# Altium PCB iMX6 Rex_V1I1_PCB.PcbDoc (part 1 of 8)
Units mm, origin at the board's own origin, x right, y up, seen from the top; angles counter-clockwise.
Board outline 70 x 40 mm, 12 copper layers (L1, L2, L3, L4, L5 (PWR), L6 (PWR), L7 (PWR), L8 (PWR), L9, L10, L11, L12), stack 1.566 mm thick; 473 components, 409 nets, 2294 pads, 1880 vias.
Unrouted connection lines stored in the file: 7.
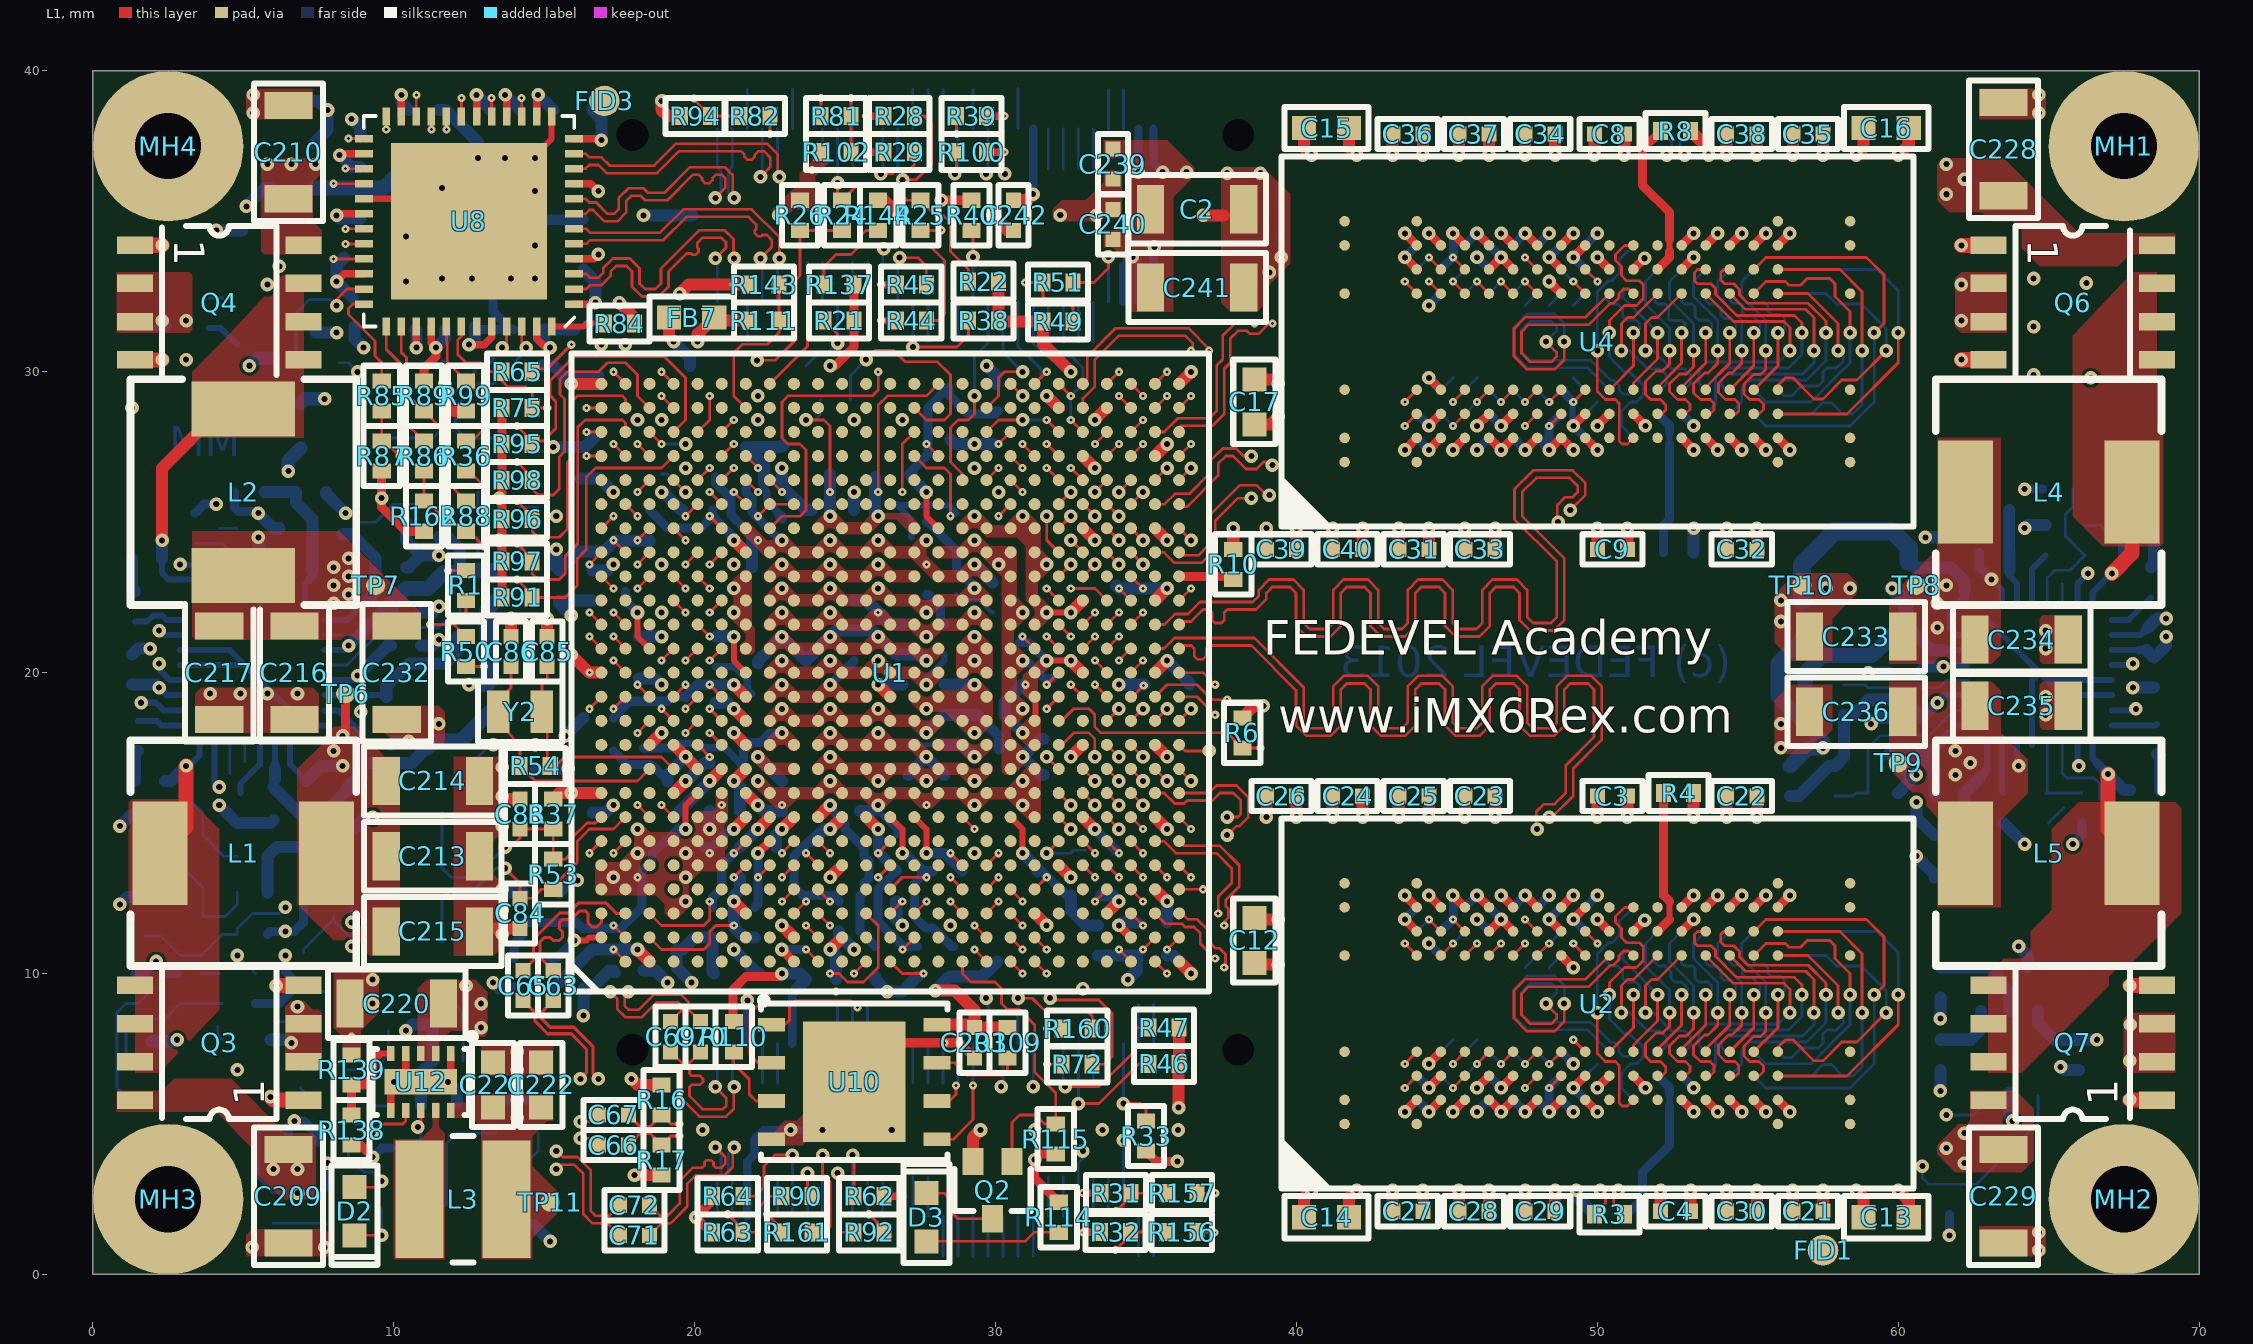
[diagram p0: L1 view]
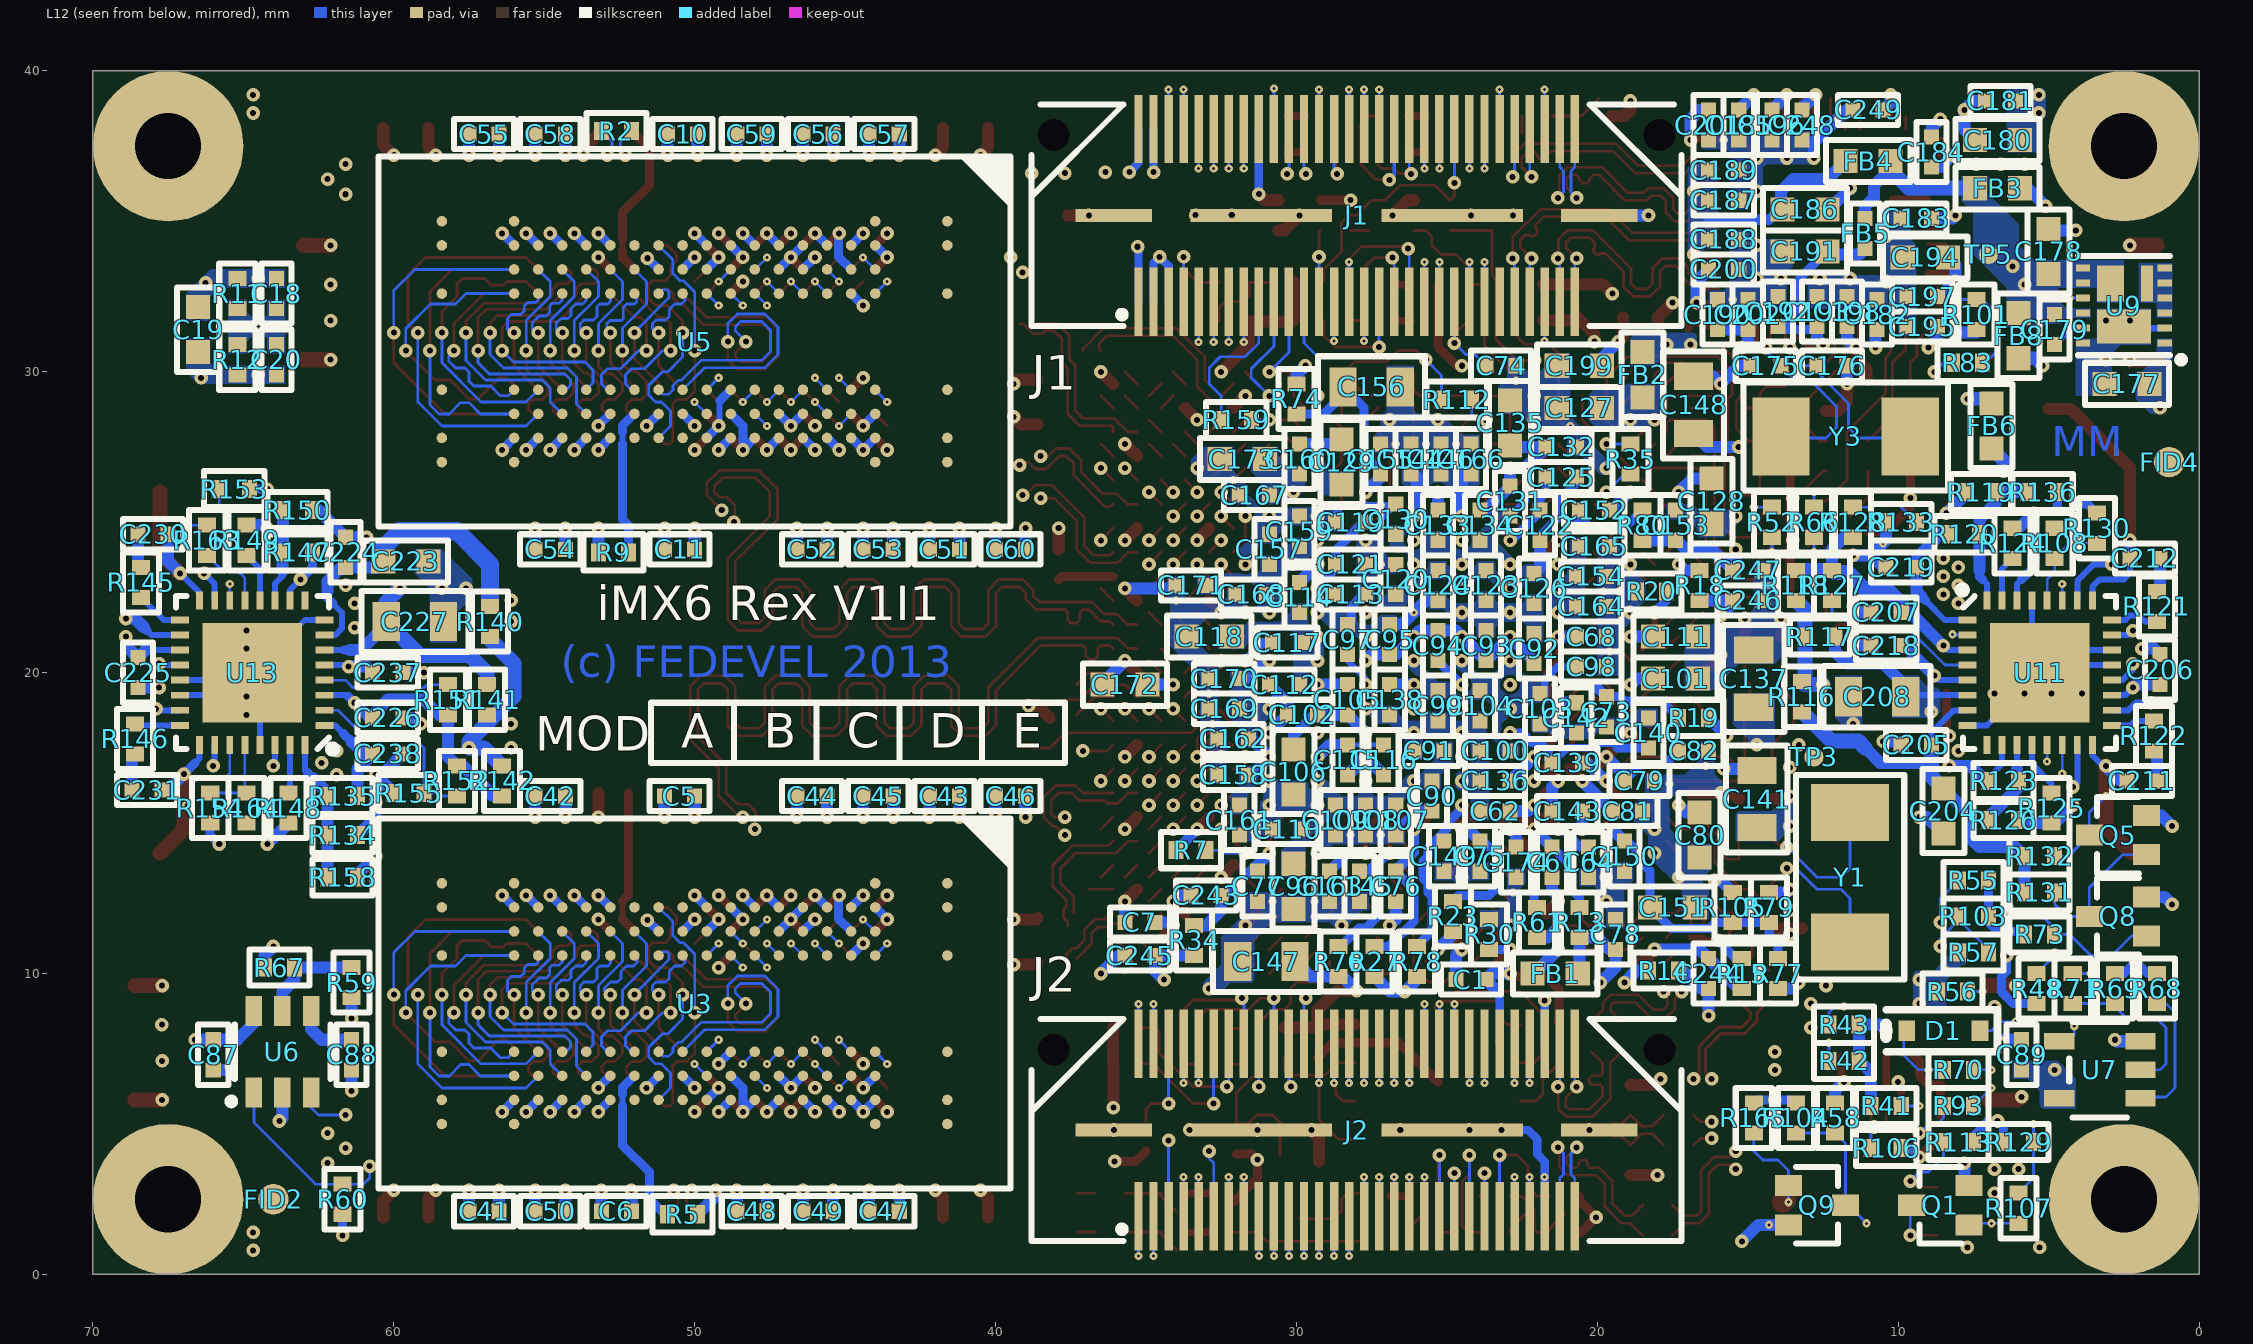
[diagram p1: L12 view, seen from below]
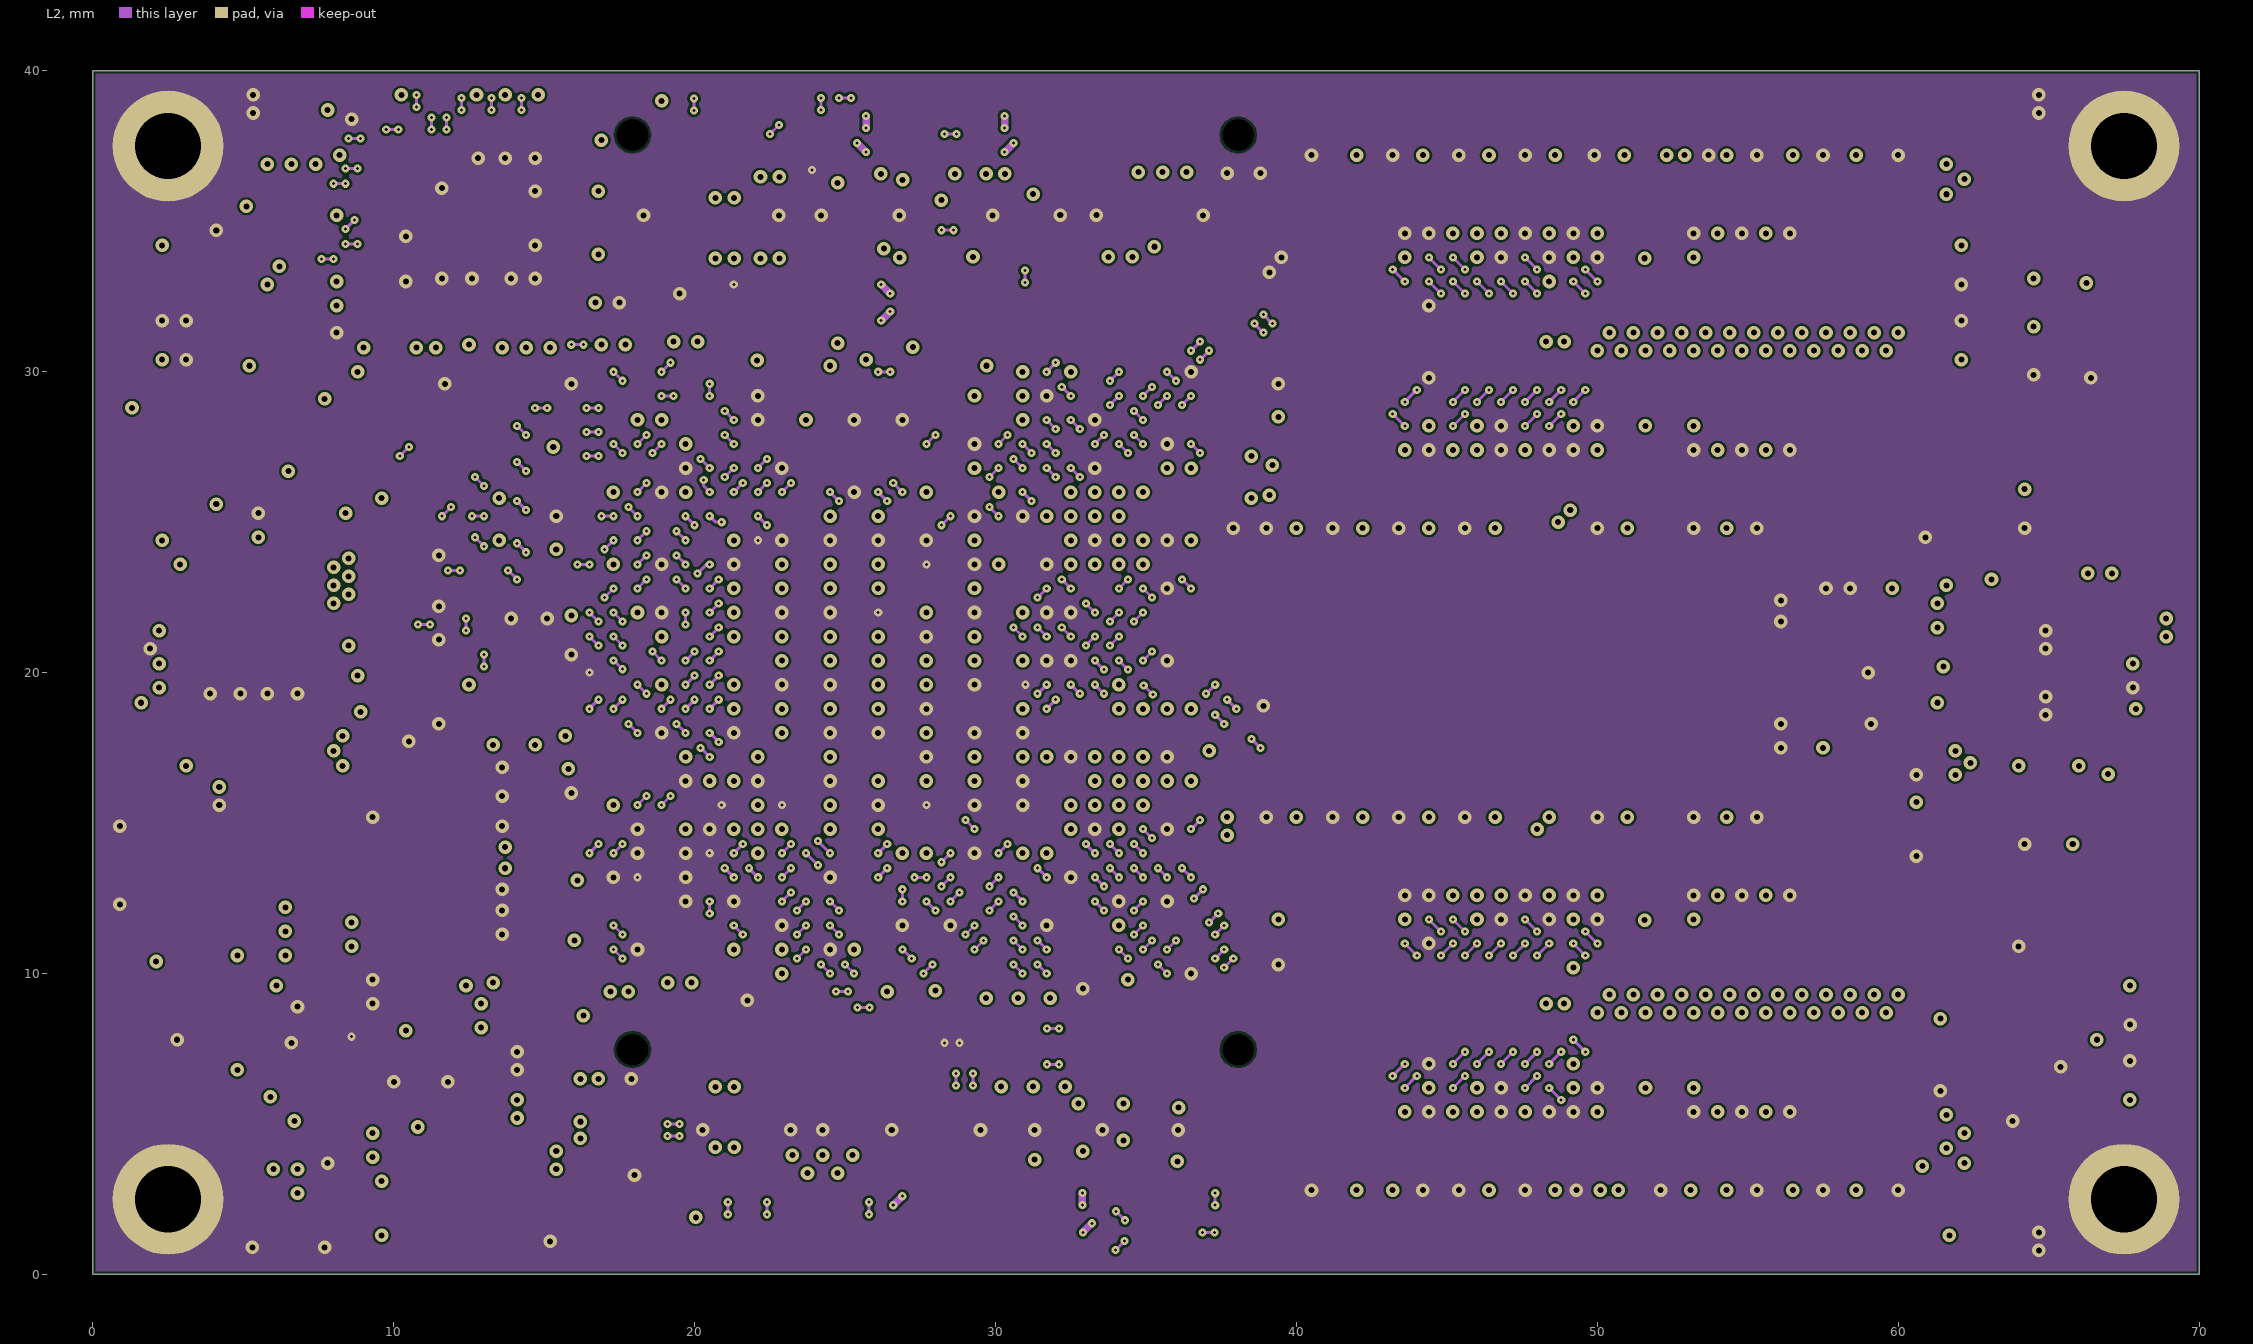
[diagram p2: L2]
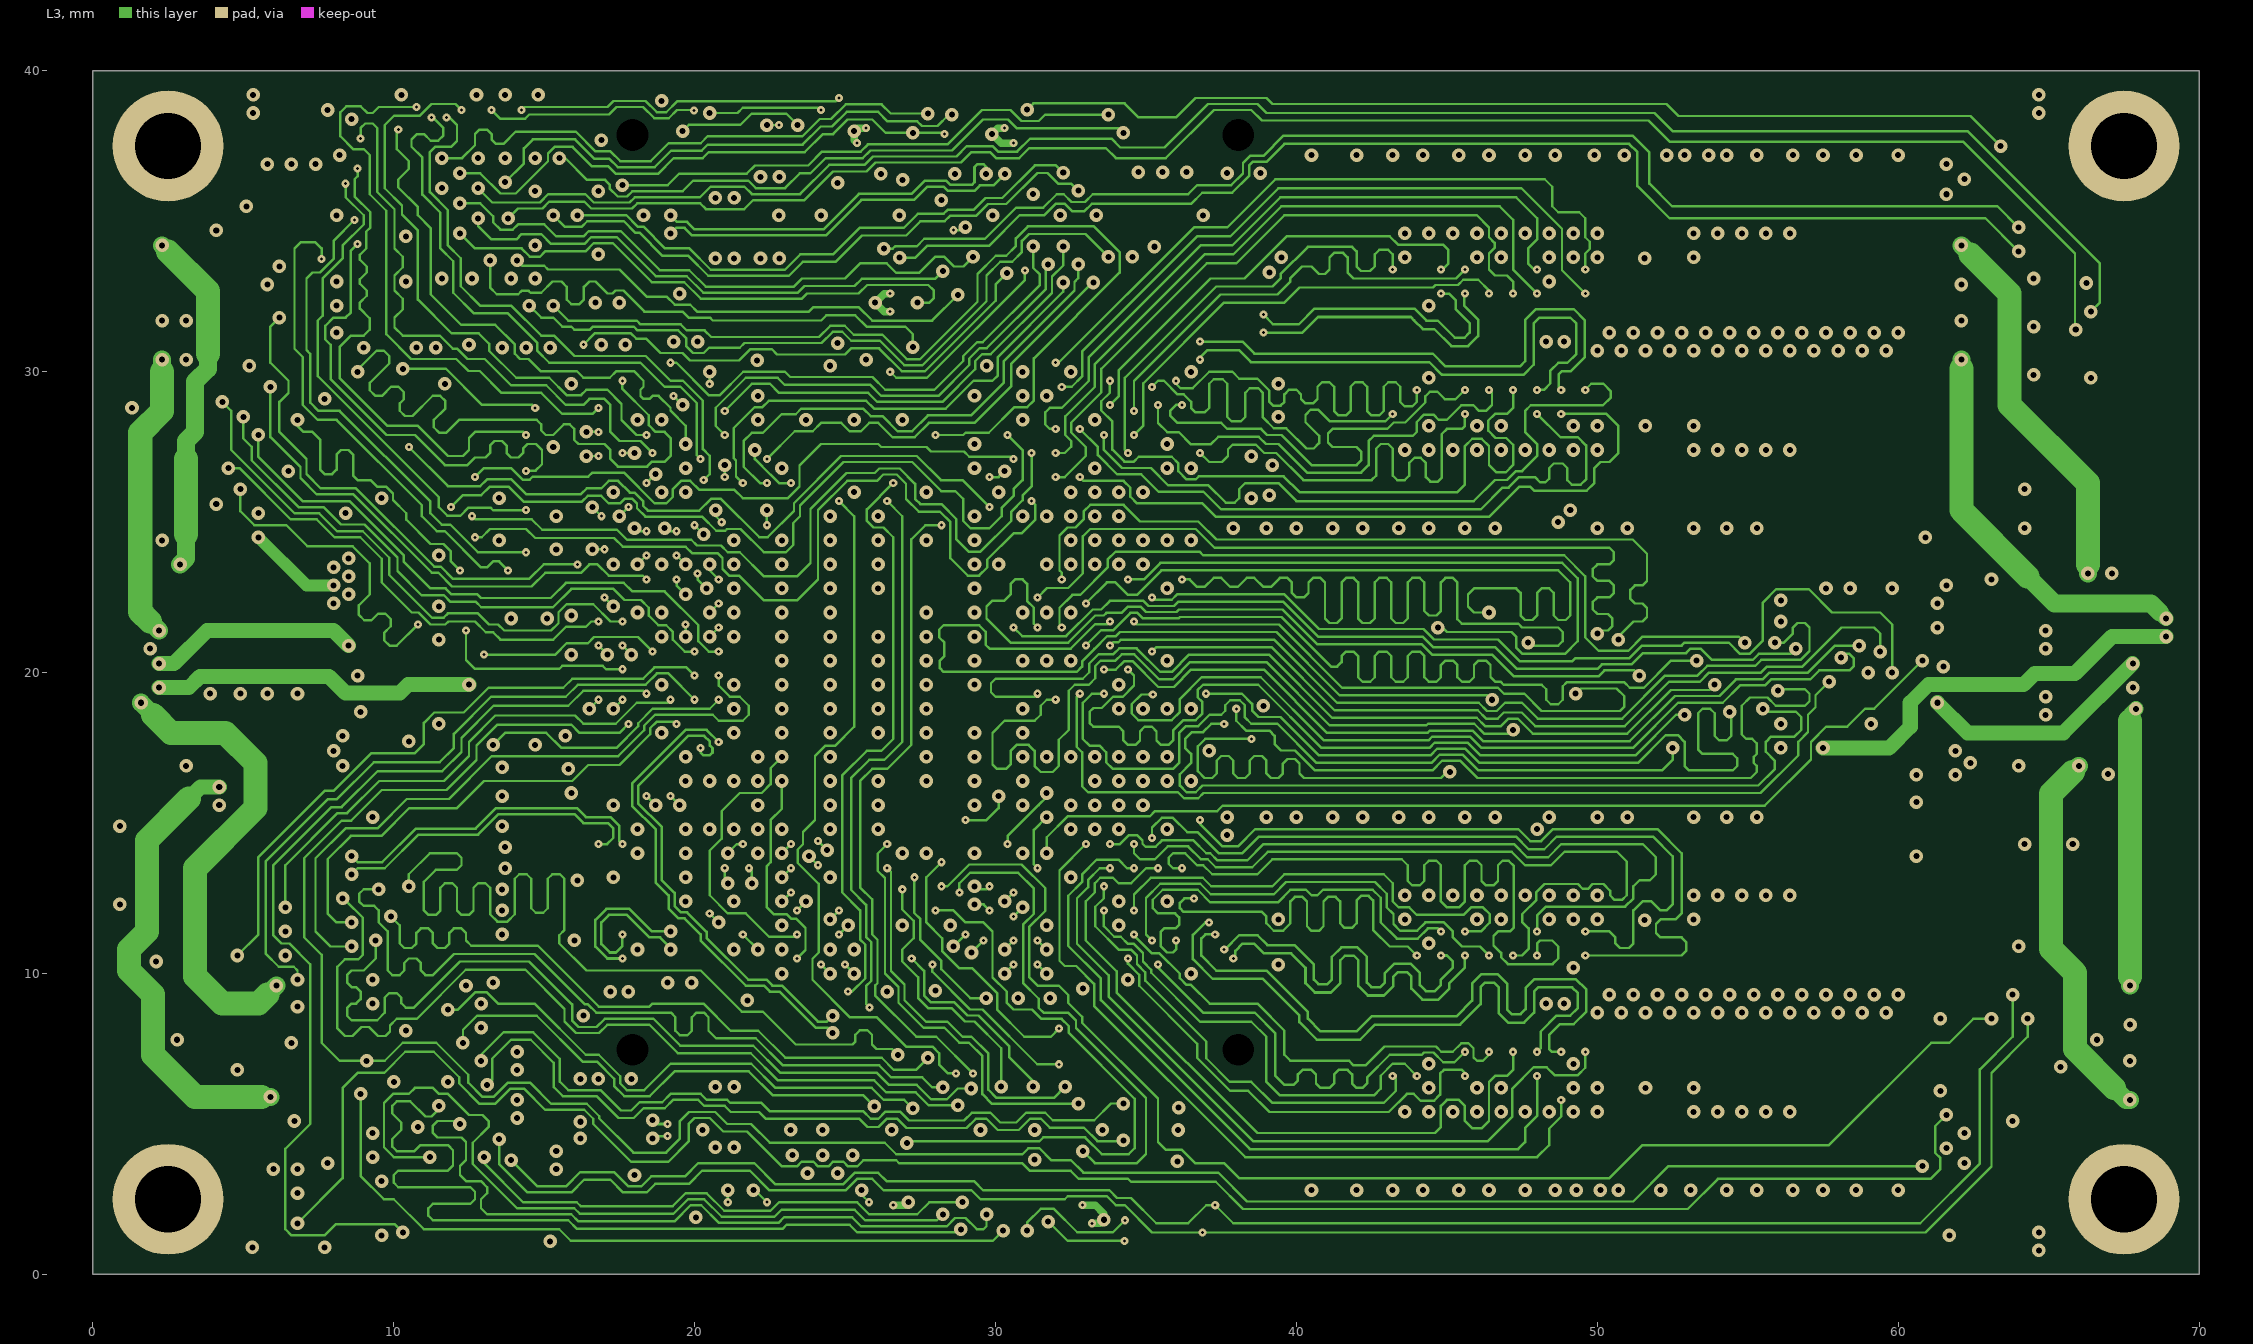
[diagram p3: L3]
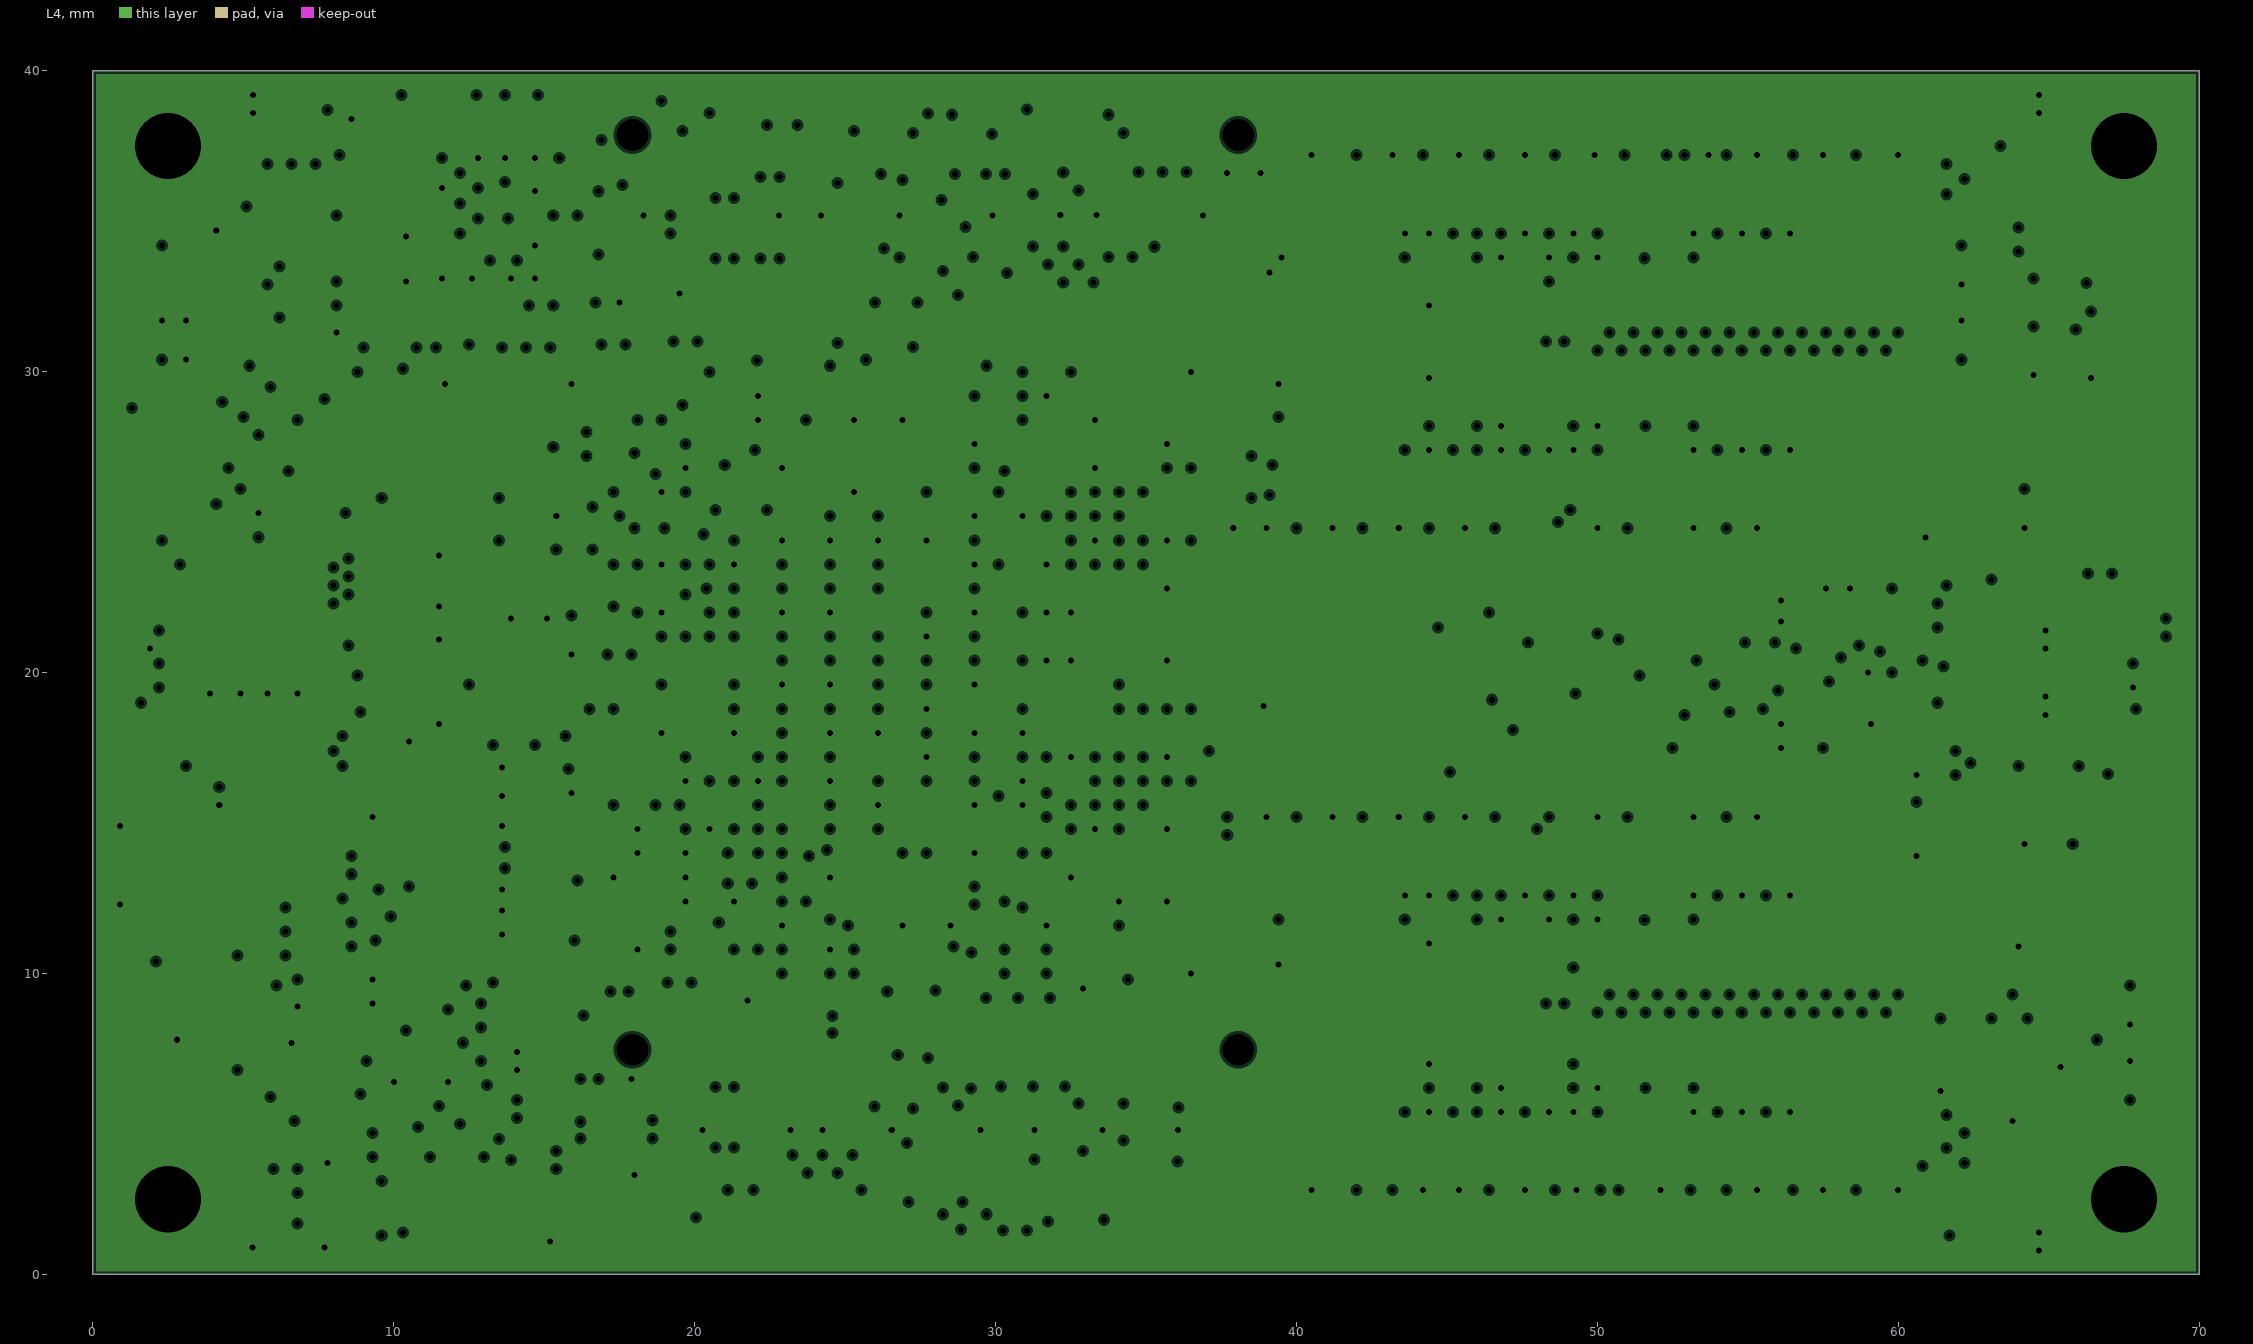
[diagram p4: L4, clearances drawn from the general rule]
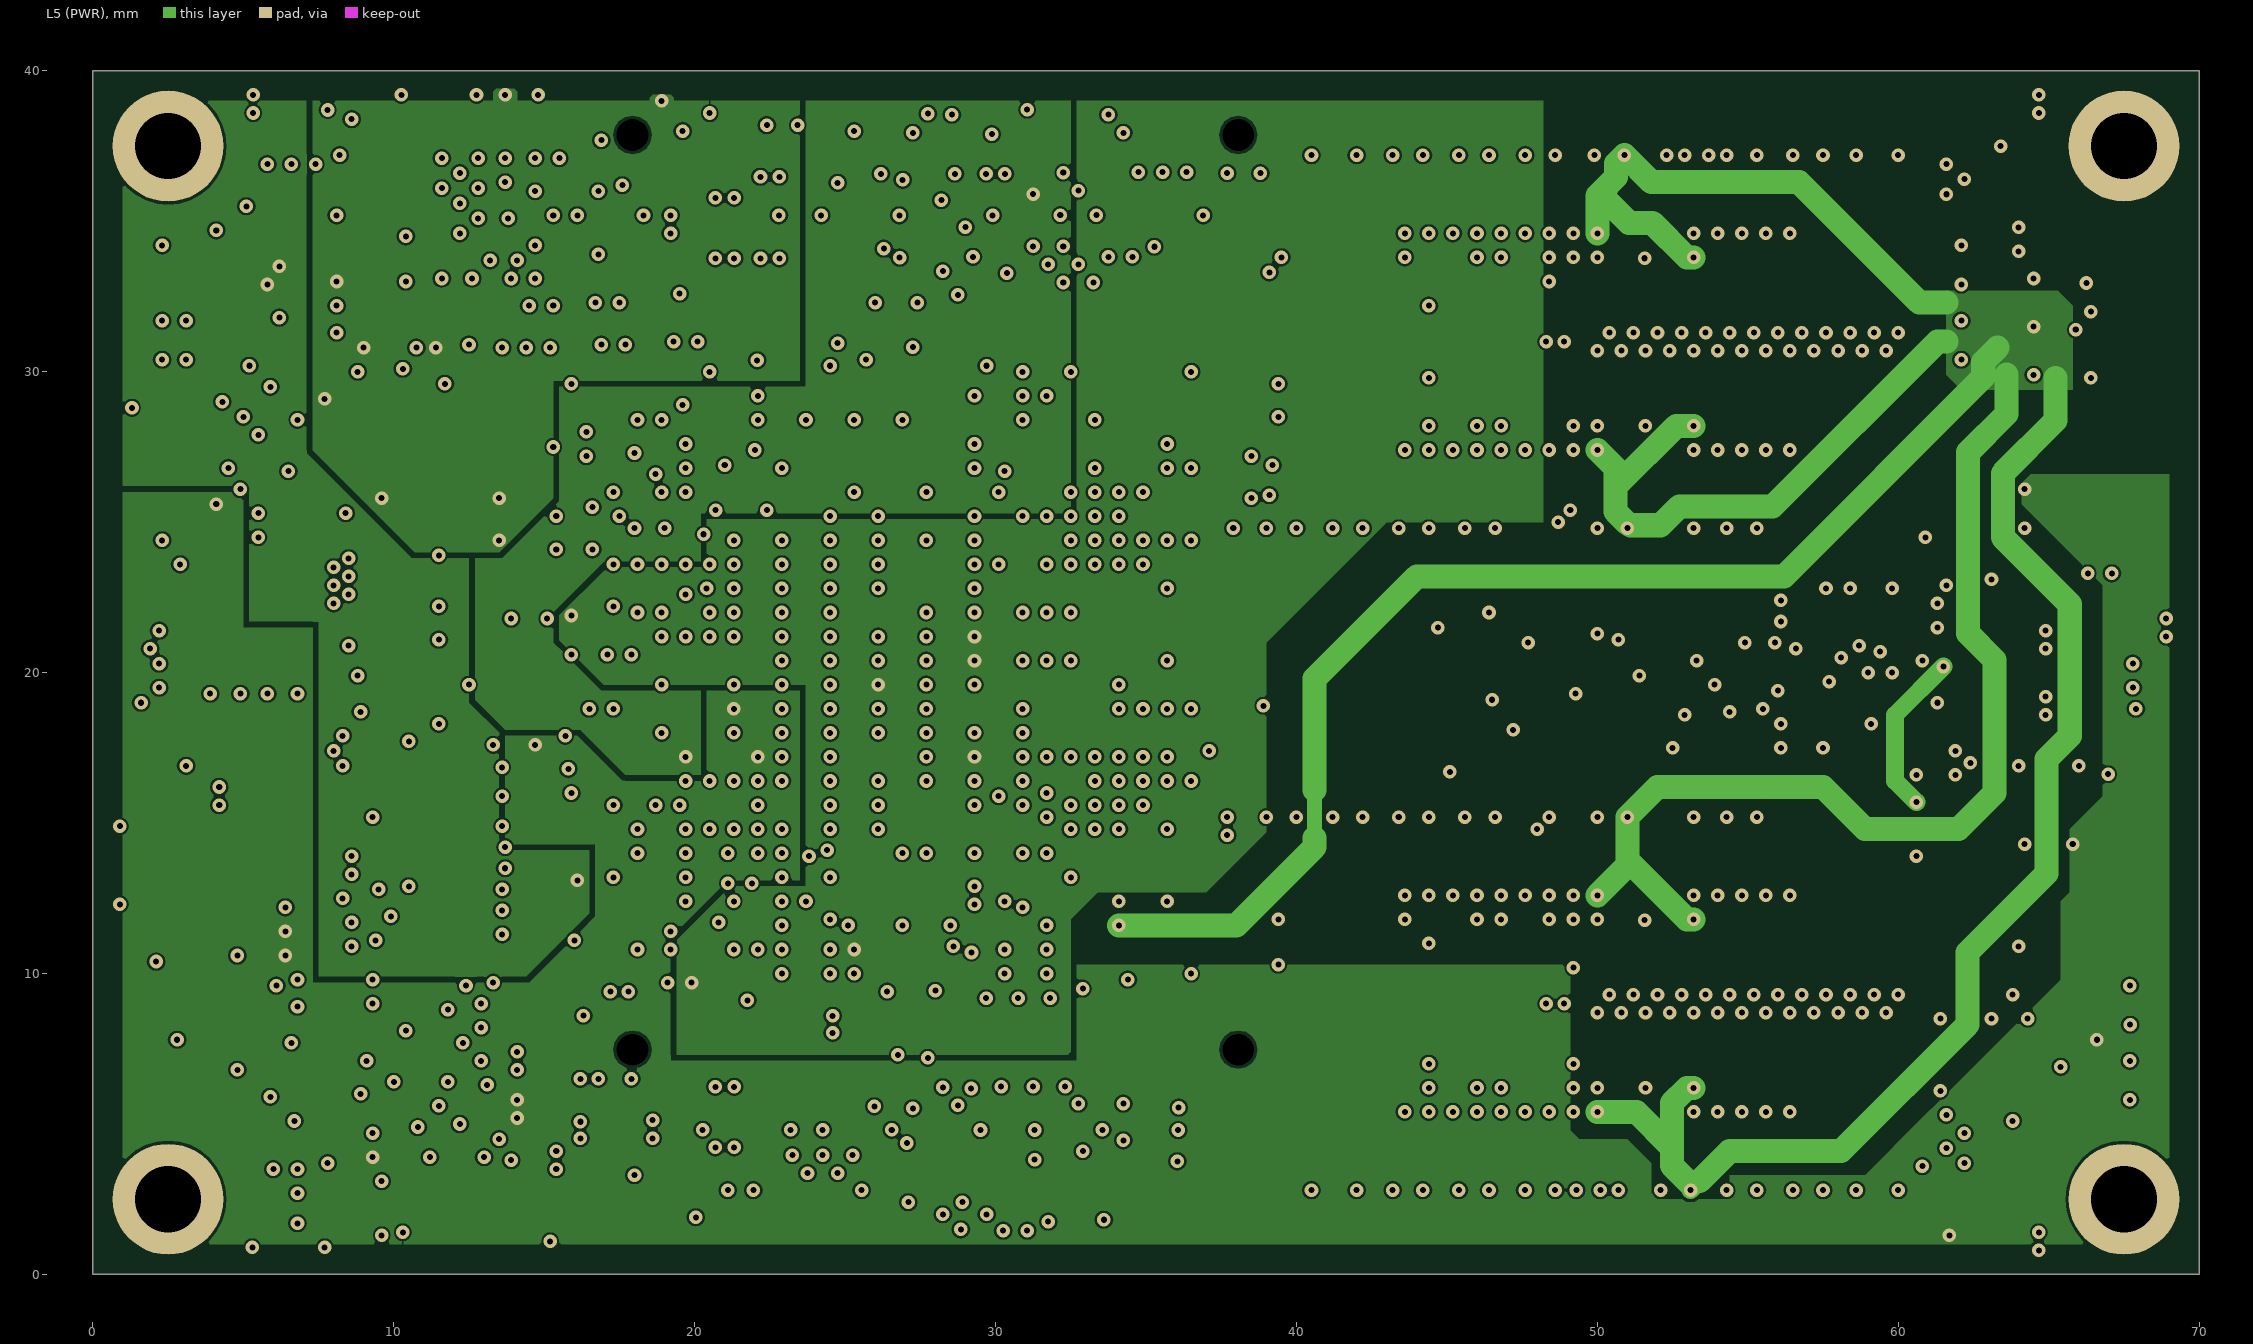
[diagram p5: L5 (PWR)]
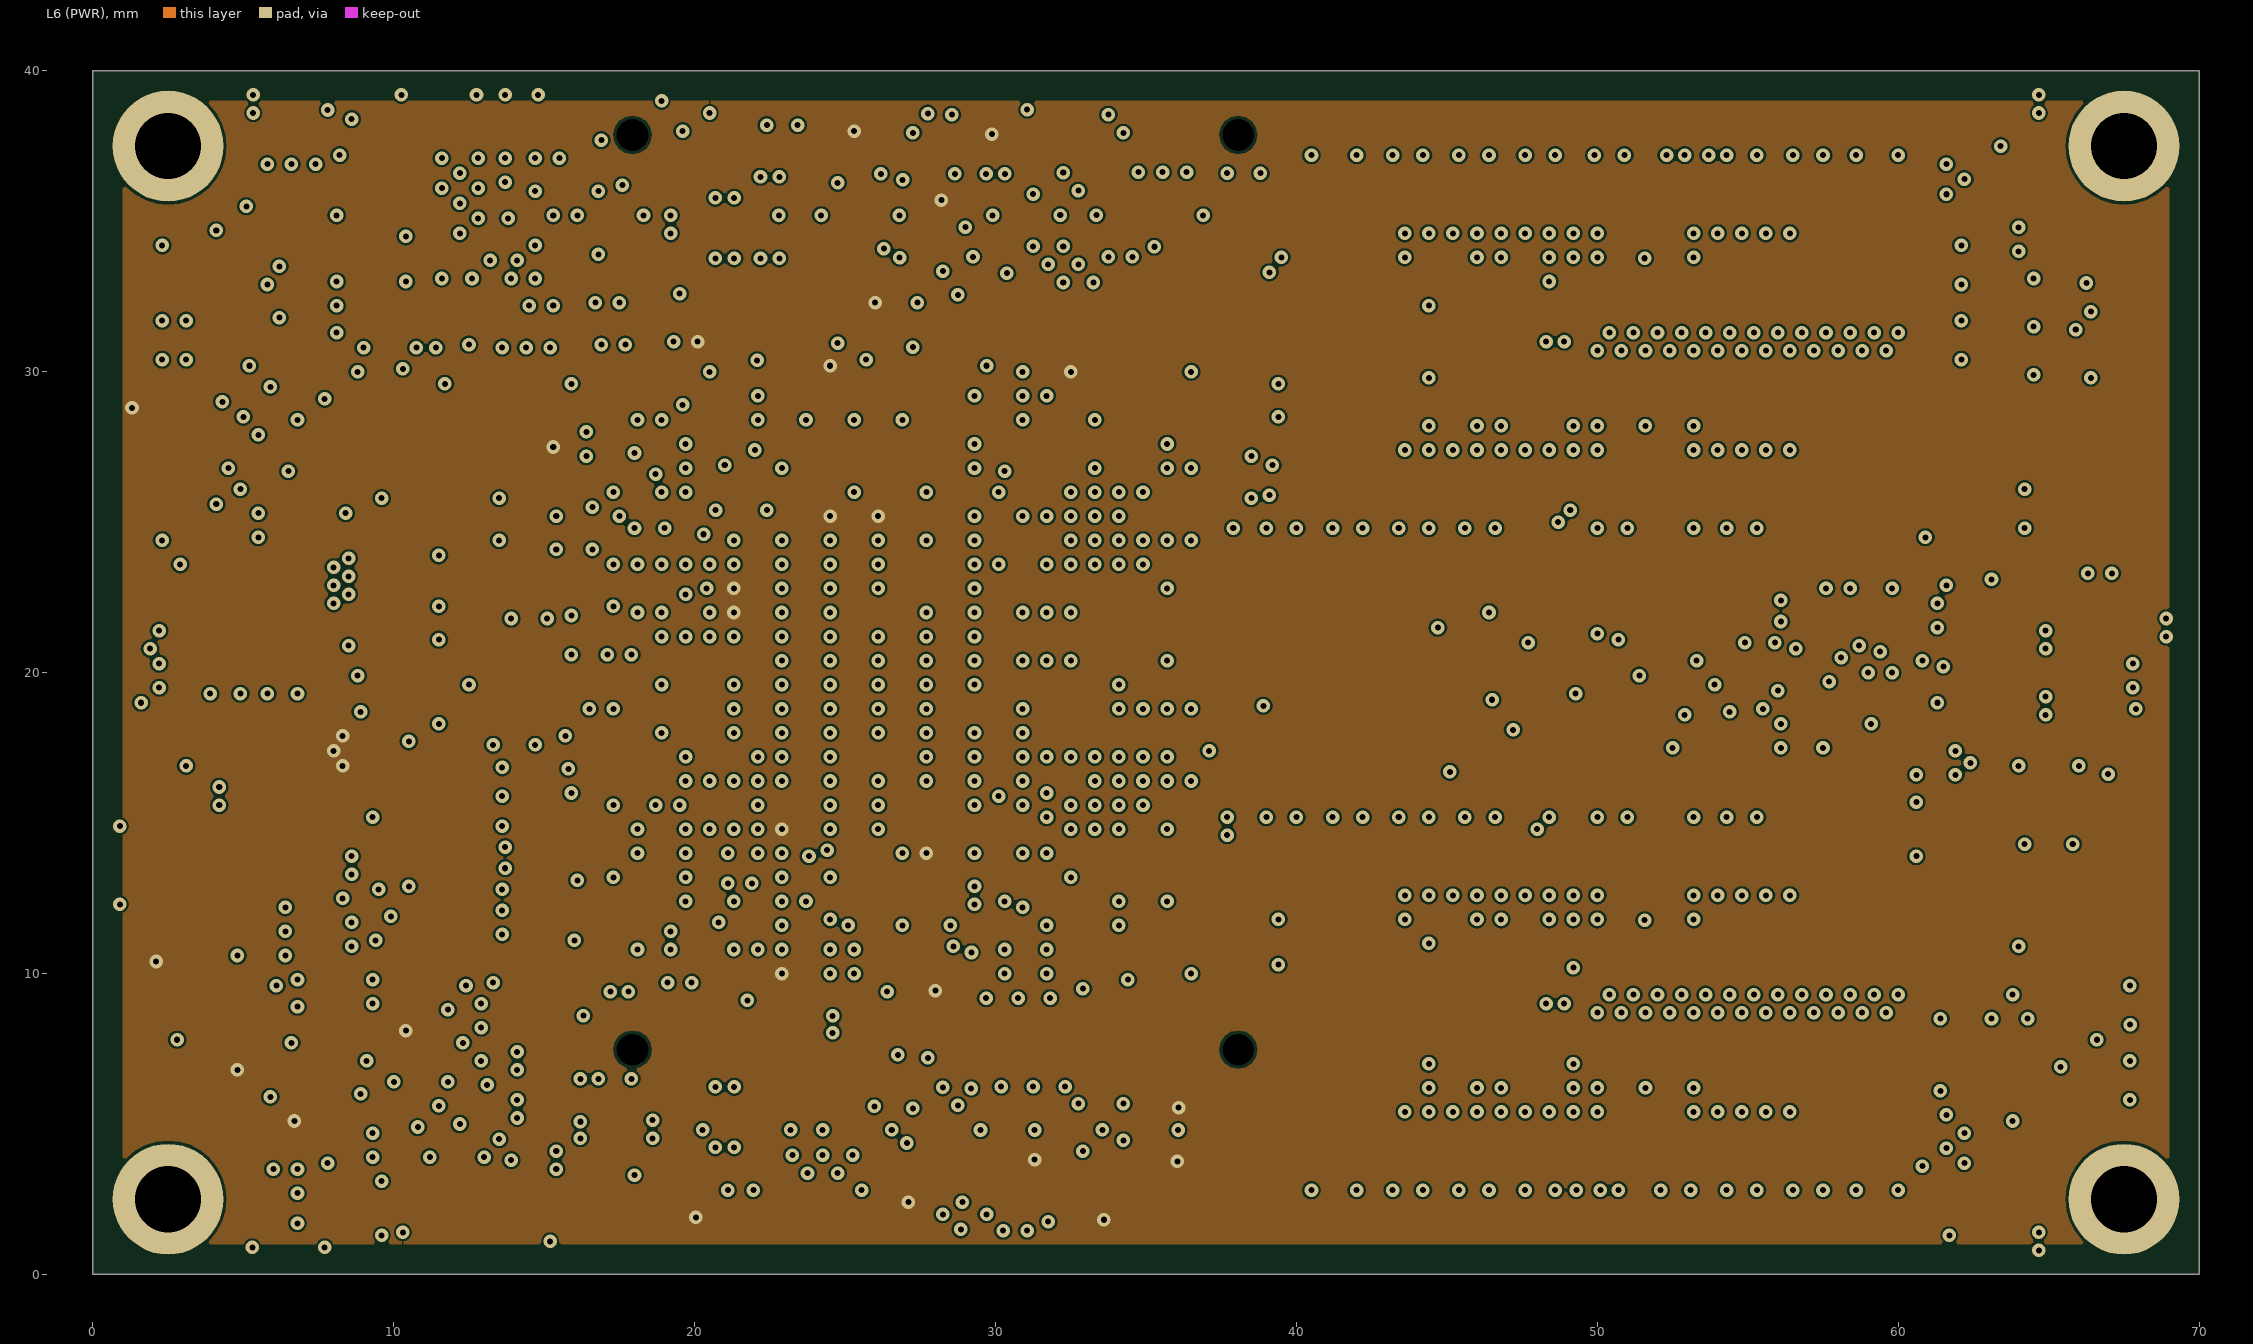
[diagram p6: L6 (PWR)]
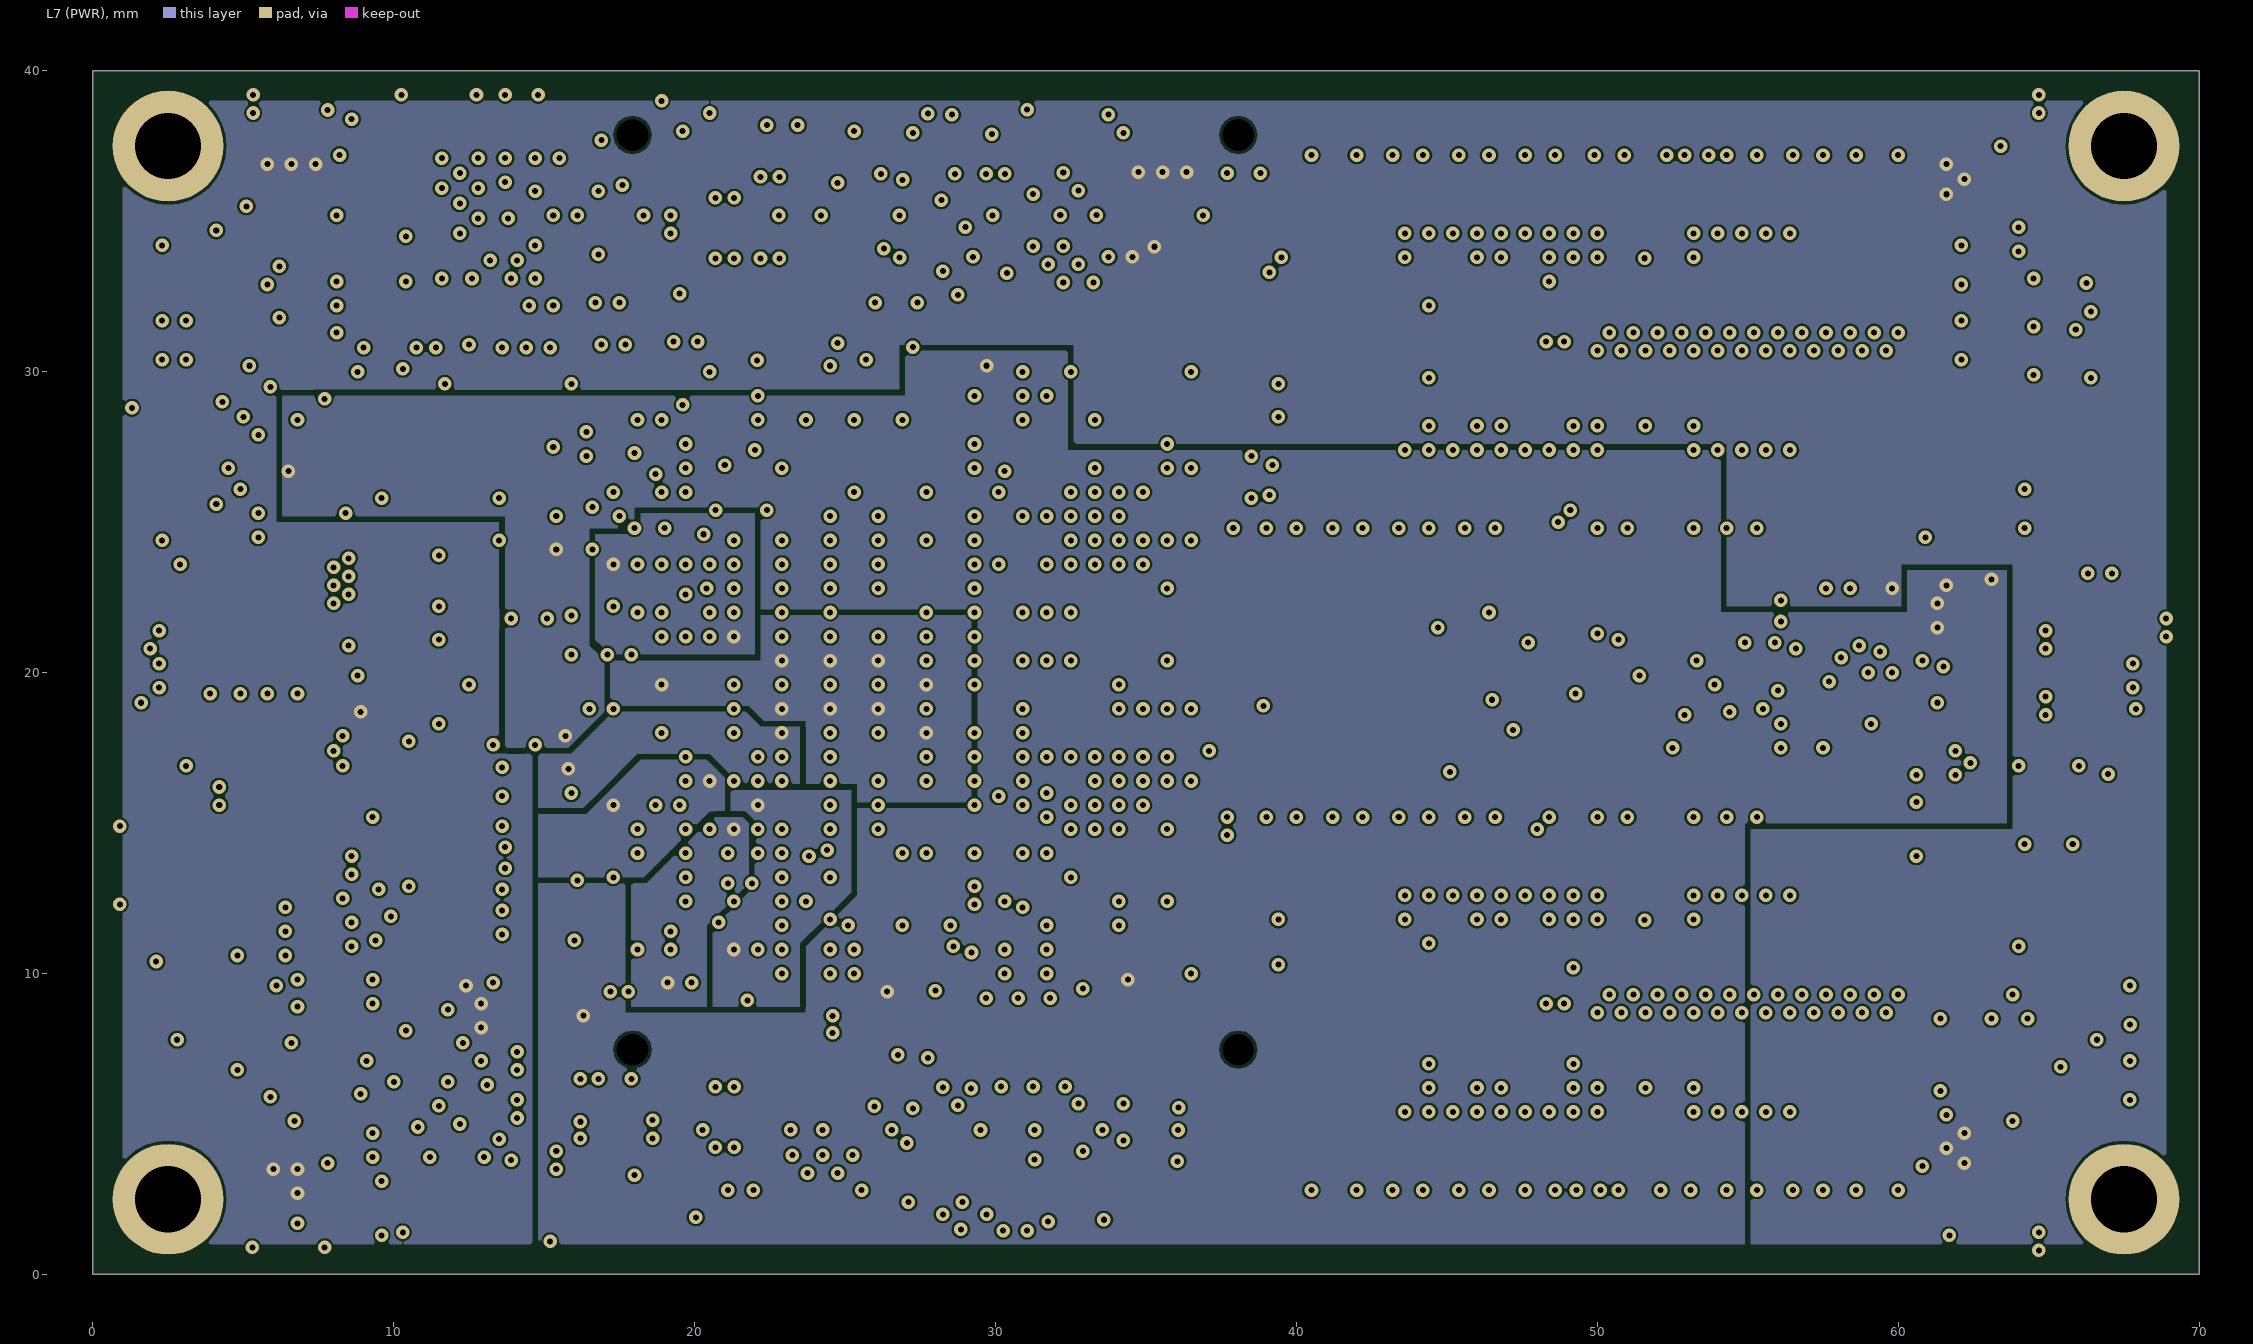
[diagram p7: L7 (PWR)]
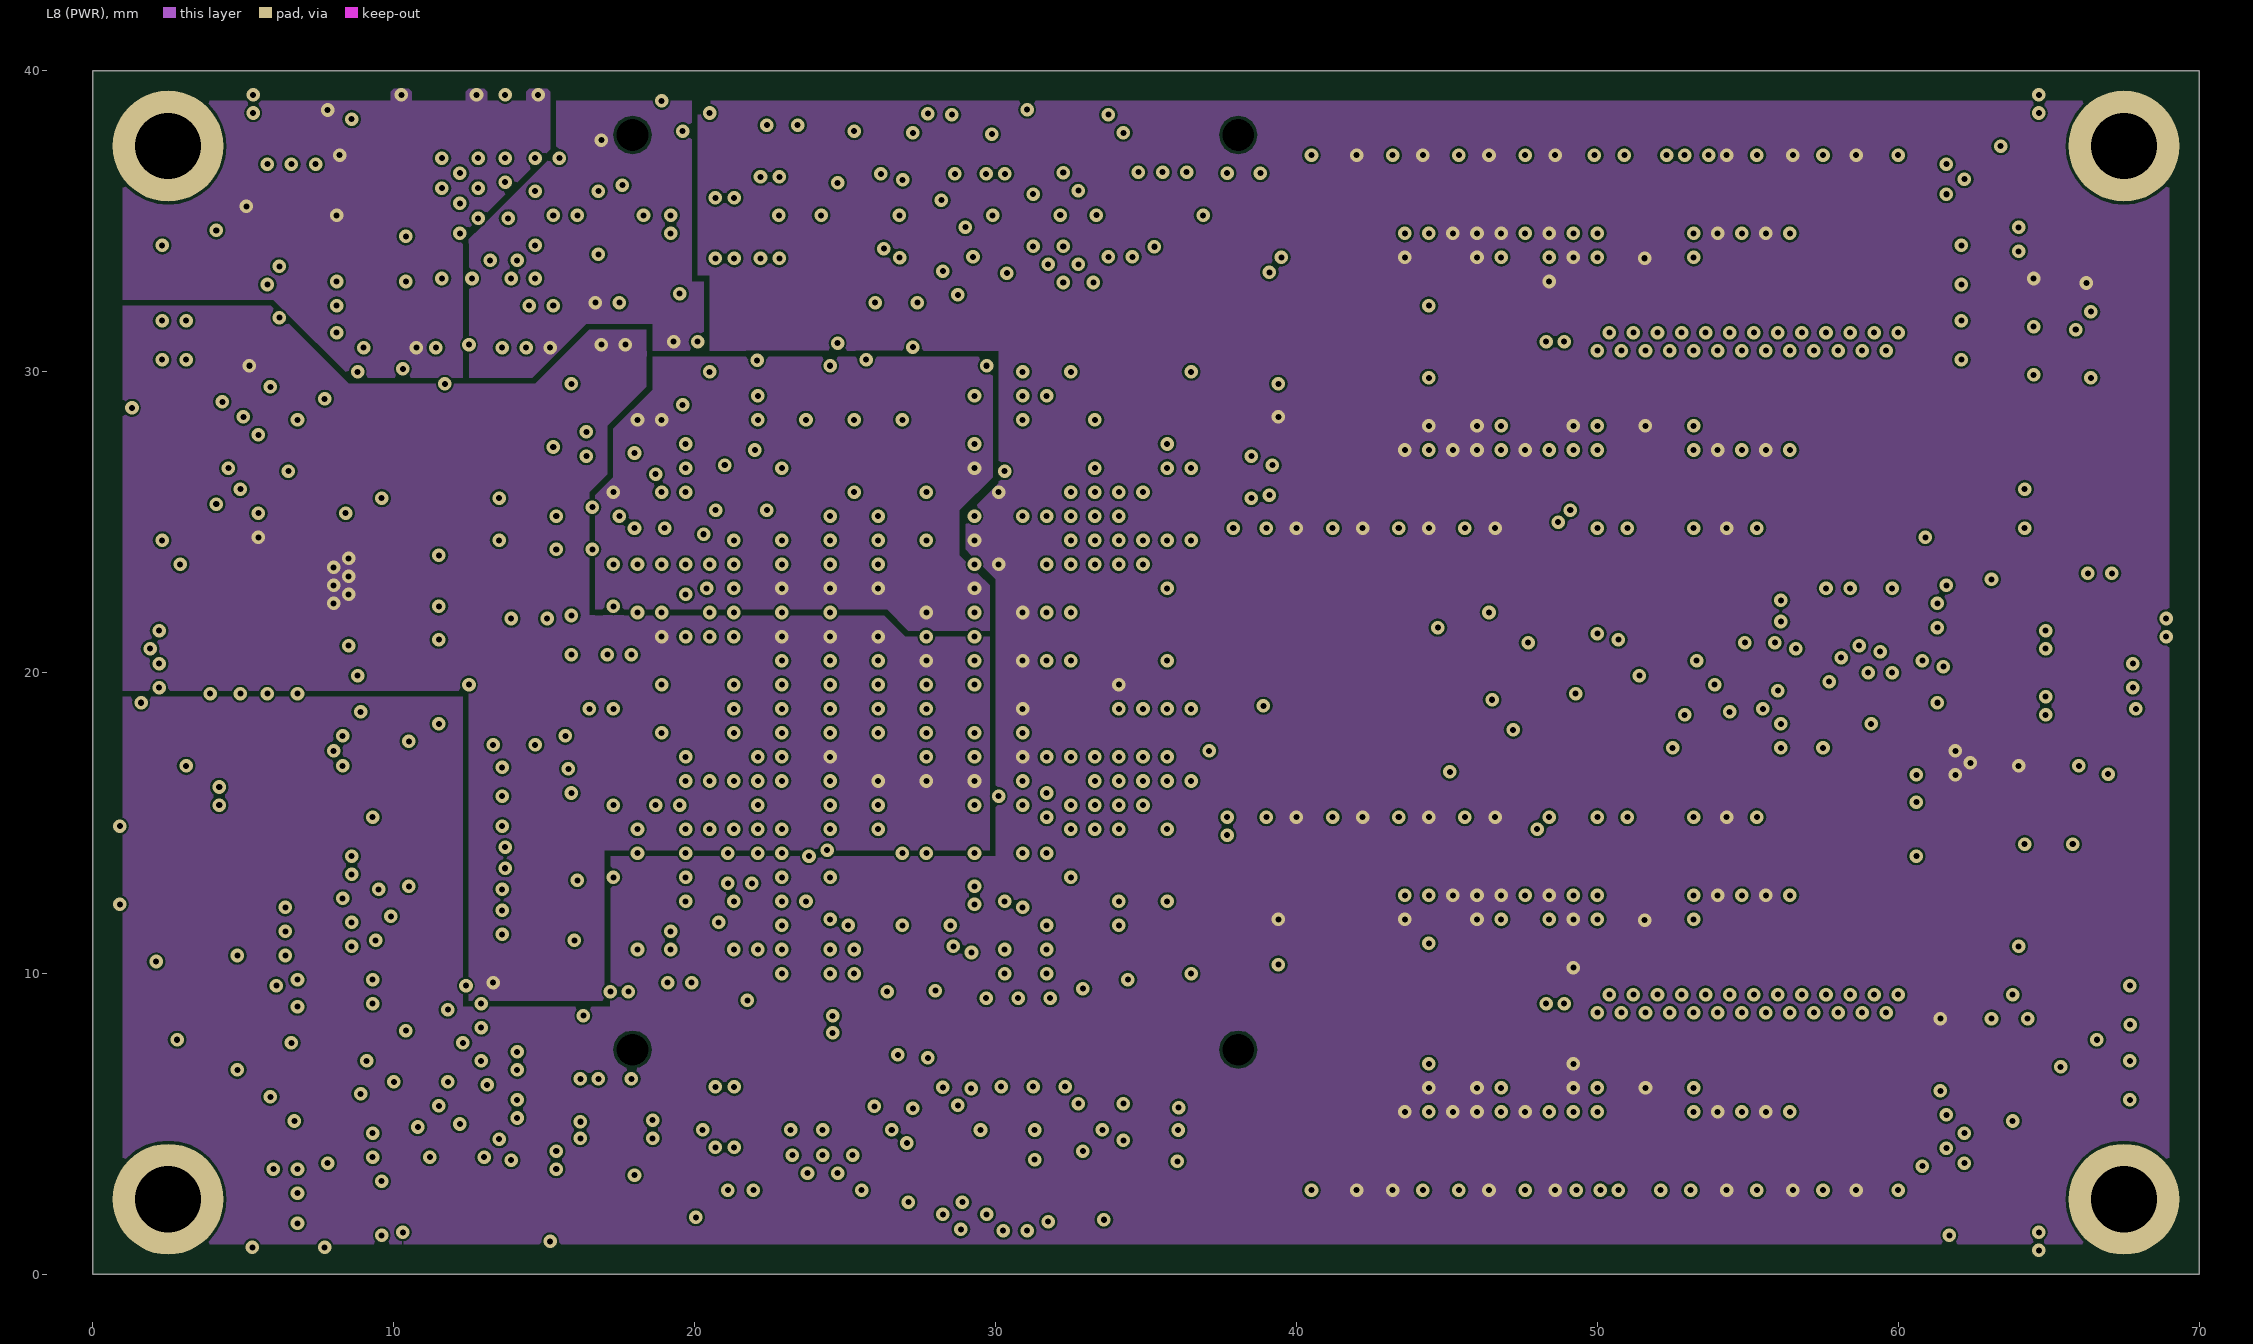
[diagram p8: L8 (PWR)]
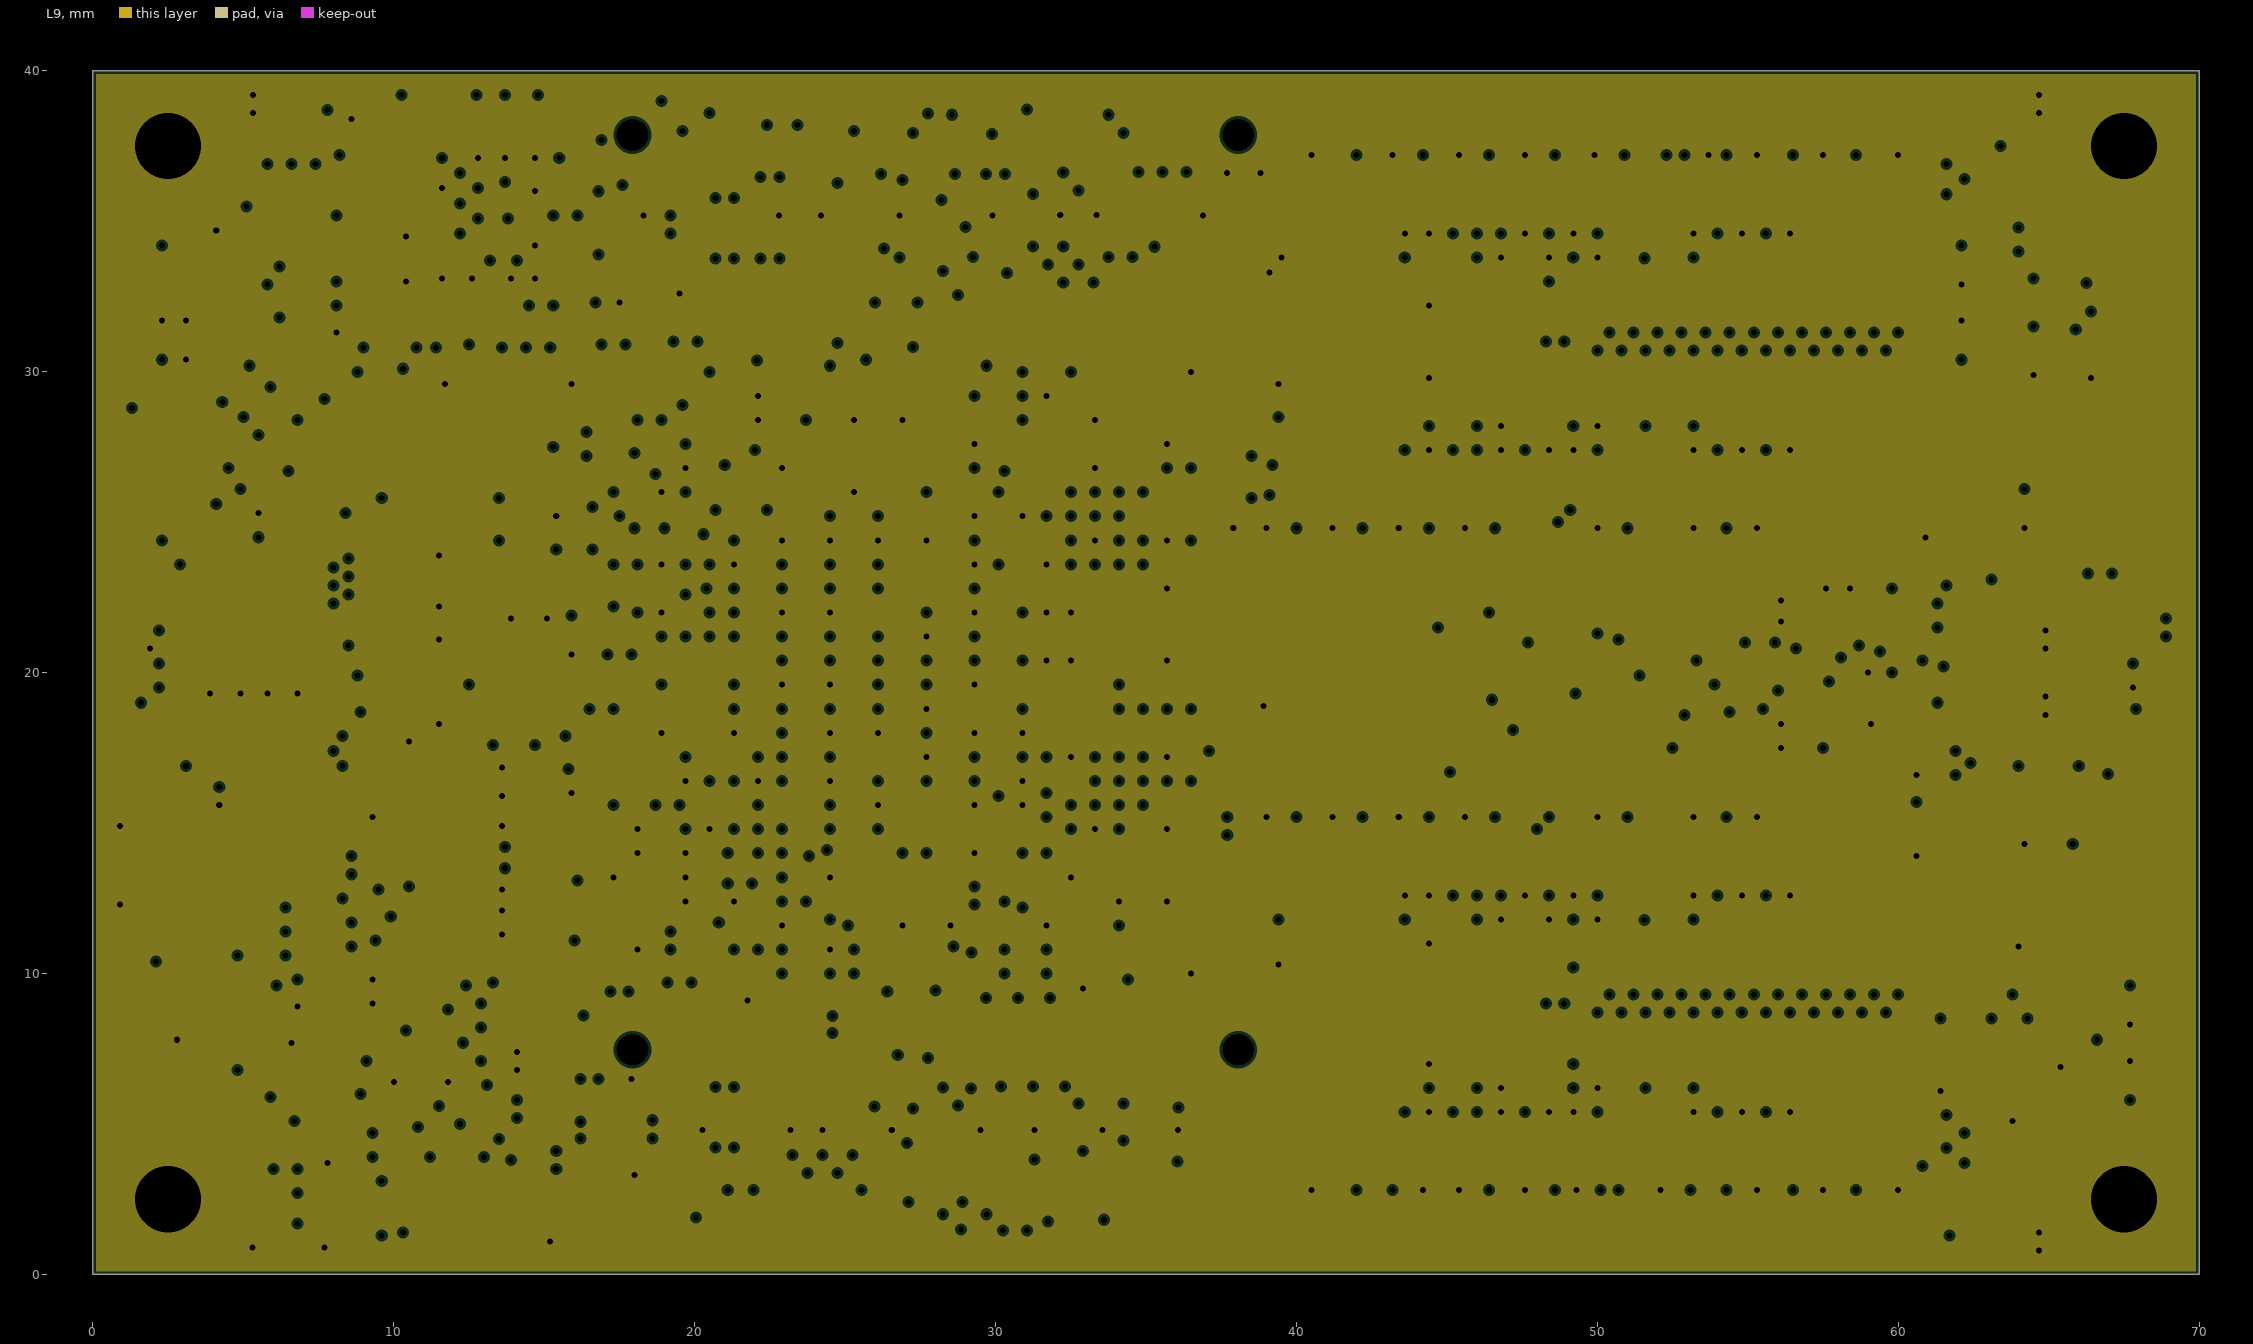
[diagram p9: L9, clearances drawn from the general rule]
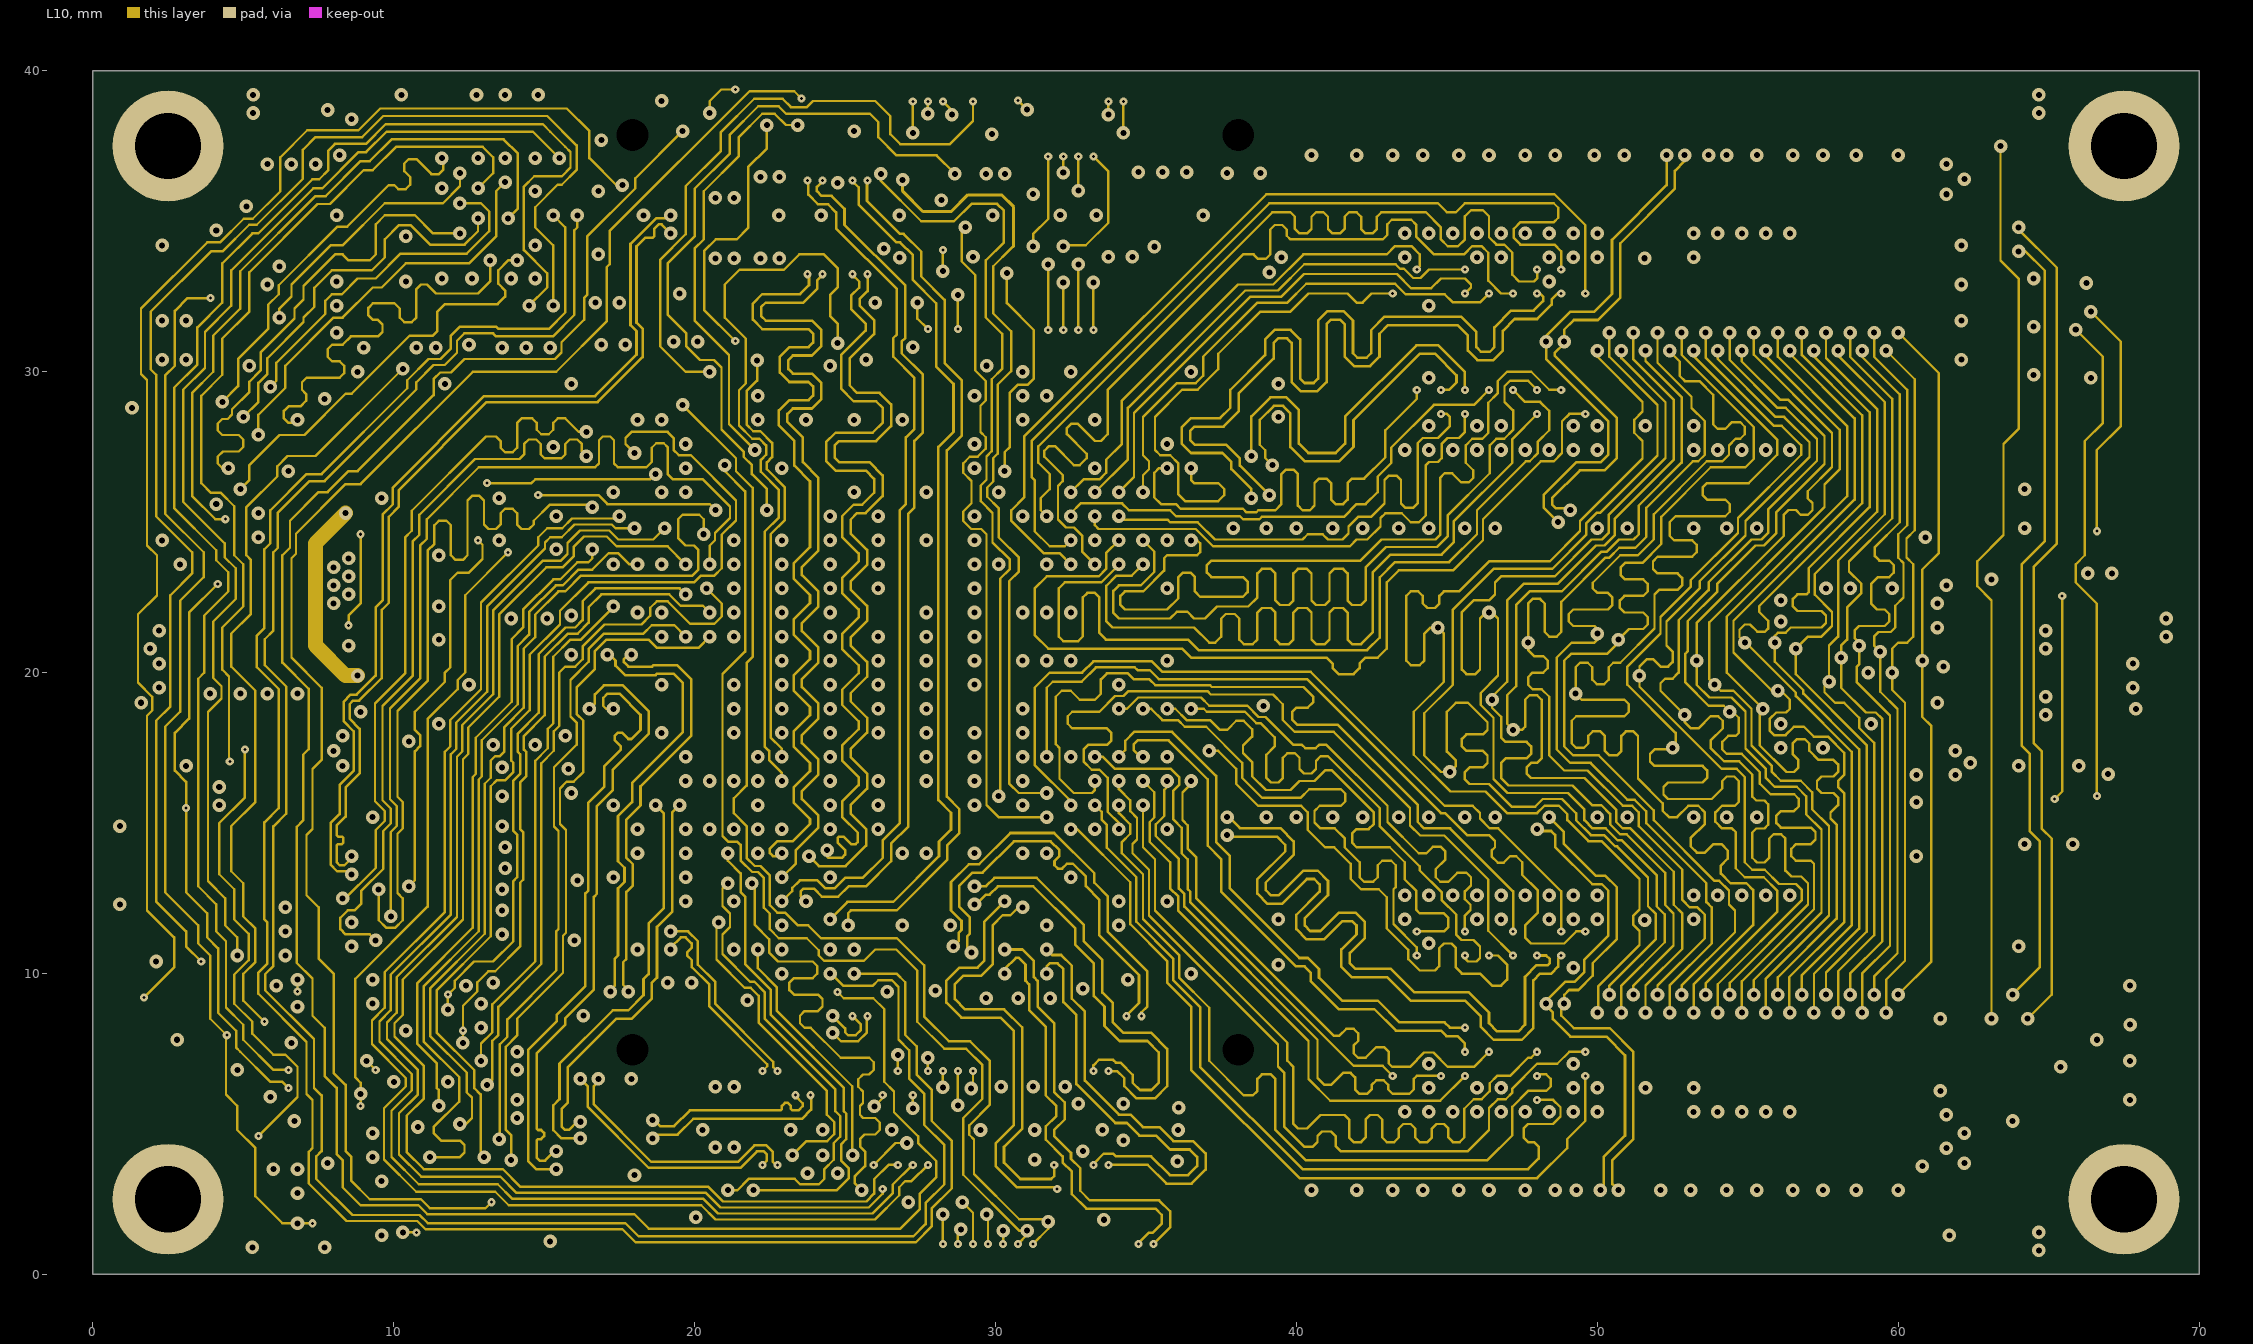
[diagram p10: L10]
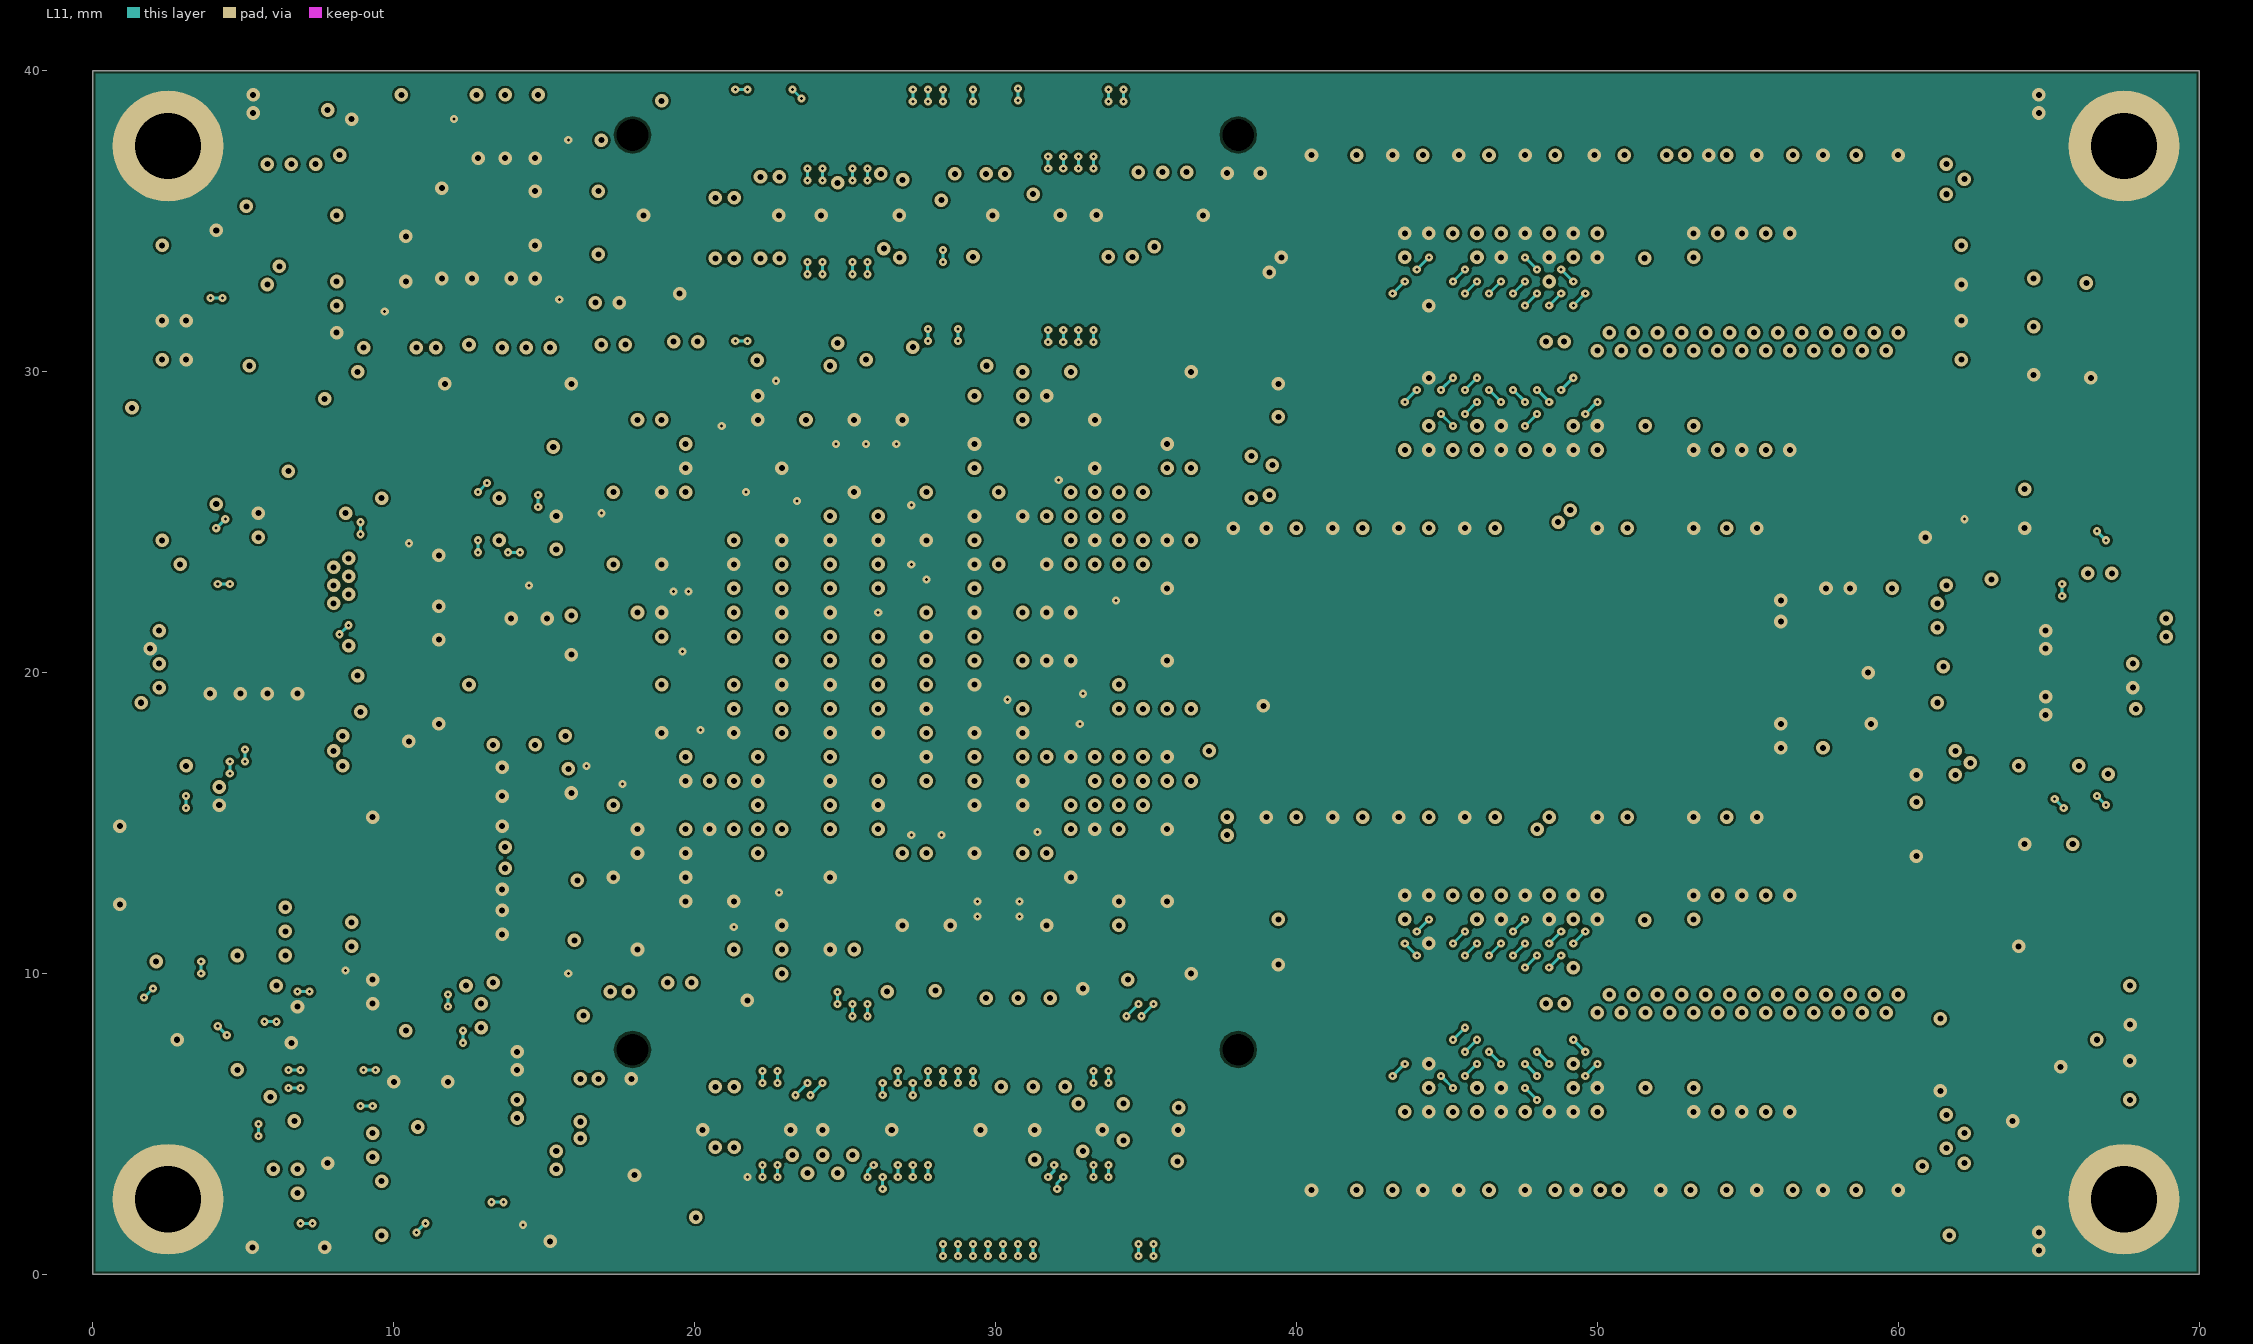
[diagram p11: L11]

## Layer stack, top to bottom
Top Solder: solder mask 0.0102, Solder Resist, Dk 3.5
L1: signal copper 0.038
Dielectric1: core 0.07, FR-4, Dk 4.8
L2: signal copper 0.038
Dielectric2: prepreg 0.092, FR-4, Dk 4.8
L3: signal copper 0.038
Dielectric3: core 0.2, FR-4, Dk 4.8
L4: plane copper 0.015, net GND
Dielectric10: prepreg 0.102, FR-4, Dk 4.8
L5 (PWR): signal copper 0.015
Dielectric9: core 0.1, FR-4, Dk 4.8
L6 (PWR): signal copper 0.015
Dielectric4: prepreg 0.118, FR-4, Dk 4.8
L7 (PWR): signal copper 0.015
Dielectric5: core 0.1, FR-4, Dk 4.8
L8 (PWR): signal copper 0.015
Dielectric8: prepreg 0.102, FR-4, Dk 4.8
L9: plane copper 0.015, net GND
Dielectric11: core 0.2, FR-4, Dk 4.8
L10: signal copper 0.038
Dielectric6: prepreg 0.093, FR-4, Dk 4.8
L11: signal copper 0.038
Dielectric7: core 0.071, FR-4, Dk 4.8
L12: signal copper 0.038
Bottom Solder: solder mask 0.0102, Solder Resist, Dk 3.5

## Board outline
0,0 0,40 70,40 70,0 0,0

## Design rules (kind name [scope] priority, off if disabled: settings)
Clearance "Poly GND to Via" [(IsRegion AND (OnLayer('L2') OR OnLayer('L11'))) vs IsVia AND (HoleSize  <> 0.1)] p1: gap=0.075
Clearance "Poly L2 & L11 to All" [(IsRegion AND (OnLayer('L2') OR OnLayer('L11')))] p2: gap=0.085
Clearance "Poly PWR to Via" [IsRegion AND (OnLayer('L5 (PWR)') OR OnLayer('L6 (PWR)') OR OnLayer('L7 (PWR)') OR OnLayer('L8 (PWR)') ) vs IsVia] p3: gap=0.075
Clearance "Poly to Poly" [IsRegion AND (OnLayer('L5 (PWR)') OR OnLayer('L6 (PWR)') OR OnLayer('L7 (PWR)') OR OnLayer('L8 (PWR)') ) vs IsRegion] p4: gap=0.2
Clearance "Clearance Plated Hole" [(InPadClass('NPTH'))] p5: gap=0.2
Clearance Clearence [All] p6: gap=0.1
ComponentClearance [All] p1: gap=0.1 collisioncheckmode=3 verticalgap=0.1 showdistances=FALSE
DiffPairsRouting DiffPair_DIFF100DiffPairsRouting [InDifferentialPairClass('DIFF100')] p1: maxlimit=0.22 minlimit=0.1 mostfreqgap=0.1 toplayer_mingap=0.135 toplayer_maxgap=0.185 toplayer_prefgap=0.16 toplayer_minwidth=0.09 toplayer_maxwidth=0.09 toplayer_prefwidth=0.09 midlayer1_maxgap=0.1 midlayer1_minwidth=0.1 midlayer1_maxwidth=0.1 midlayer1_prefwidth=0.1 midlayer2_mingap=0.17 midlayer2_prefgap=0.195 midlayer2_minwidth=0.085 midlayer2_maxwidth=0.085 midlayer2_prefwidth=0.085 midlayer3_maxgap=0.1 midlayer3_minwidth=0.1 midlayer3_maxwidth=0.1 midlayer3_prefwidth=0.1 midlayer4_maxgap=0.1 midlayer4_minwidth=0.1 midlayer4_maxwidth=0.1 midlayer4_prefwidth=0.1 midlayer5_mingap=0.17 midlayer5_prefgap=0.195 midlayer5_minwidth=0.085 midlayer5_maxwidth=0.085 midlayer5_prefwidth=0.085 midlayer6_maxgap=0.1 midlayer6_minwidth=0.1 midlayer6_maxwidth=0.1 midlayer6_prefwidth=0.1 midlayer7_maxgap=0.1 midlayer7_minwidth=0.1 midlayer7_maxwidth=0.1 midlayer7_prefwidth=0.1 midlayer8_maxgap=0.1 midlayer8_minwidth=0.1 midlayer8_maxwidth=0.1 midlayer8_prefwidth=0.1 bottomlayer_mingap=0.135 bottomlayer_maxgap=0.185 bottomlayer_prefgap=0.16 bottomlayer_minwidth=0.09 bottomlayer_maxwidth=0.09 bottomlayer_prefwidth=0.09 maxuncoupledlength=8.7
DiffPairsRouting DiffPair_DIFF90DiffPairsRouting [InDifferentialPairClass('DIFF90')] p2: maxlimit=0.19 minlimit=0.1 mostfreqgap=0.1 toplayer_mingap=0.109 toplayer_prefgap=0.114 toplayer_minwidth=0.101 toplayer_maxwidth=0.101 toplayer_prefwidth=0.101 midlayer1_maxgap=0.1 midlayer1_minwidth=0.1 midlayer1_maxwidth=0.1 midlayer1_prefwidth=0.1 midlayer2_mingap=0.11 midlayer2_maxgap=0.12 midlayer2_prefgap=0.115 midlayer2_minwidth=0.085 midlayer2_maxwidth=0.085 midlayer2_prefwidth=0.085 midlayer3_maxgap=0.1 midlayer3_minwidth=0.1 midlayer3_maxwidth=0.1 midlayer3_prefwidth=0.1 midlayer4_maxgap=0.1 midlayer4_minwidth=0.1 midlayer4_maxwidth=0.1 midlayer4_prefwidth=0.1 midlayer5_mingap=0.11 midlayer5_maxgap=0.12 midlayer5_prefgap=0.115 midlayer5_minwidth=0.085 midlayer5_maxwidth=0.085 midlayer5_prefwidth=0.085 midlayer6_maxgap=0.1 midlayer6_minwidth=0.1 midlayer6_maxwidth=0.1 midlayer6_prefwidth=0.1 midlayer7_maxgap=0.1 midlayer7_minwidth=0.1 midlayer7_maxwidth=0.1 midlayer7_prefwidth=0.1 midlayer8_maxgap=0.1 midlayer8_minwidth=0.1 midlayer8_maxwidth=0.1 midlayer8_prefwidth=0.1 bottomlayer_mingap=0.109 bottomlayer_maxgap=0.119 bottomlayer_prefgap=0.114 bottomlayer_minwidth=0.101 bottomlayer_maxwidth=0.101 bottomlayer_prefwidth=0.101 maxuncoupledlength=8
DiffPairsRouting [All] p3: maxlimit=0.1 minlimit=0.1 mostfreqgap=0.1 toplayer_minwidth=0.381 toplayer_maxwidth=0.381 toplayer_prefwidth=0.381 midlayer1_minwidth=0.381 midlayer1_maxwidth=0.381 midlayer1_prefwidth=0.381 midlayer2_minwidth=0.381 midlayer2_maxwidth=0.381 midlayer2_prefwidth=0.381 midlayer3_minwidth=0.381 midlayer3_maxwidth=0.381 midlayer3_prefwidth=0.381 midlayer4_minwidth=0.381 midlayer4_maxwidth=0.381 midlayer4_prefwidth=0.381 midlayer5_minwidth=0.381 midlayer5_maxwidth=0.381 midlayer5_prefwidth=0.381 midlayer6_minwidth=0.381 midlayer6_maxwidth=0.381 midlayer6_prefwidth=0.381 midlayer7_minwidth=0.381 midlayer7_maxwidth=0.381 midlayer7_prefwidth=0.381 midlayer8_minwidth=0.381 midlayer8_maxwidth=0.381 midlayer8_prefwidth=0.381 bottomlayer_minwidth=0.381 bottomlayer_maxwidth=0.381 bottomlayer_prefwidth=0.381 maxuncoupledlength=12.7
HoleSize [All] p1: absolutevalues=TRUE maxlimit=6 minlimit=0.025 maxpercent=80.000 minpercent=20.000
HoleToHoleClearance [All] p1: gap=0.1 allowstackedmicrovias=TRUE
MatchedLengths DiffPair_DIFF100MatchedLengths [InDifferentialPairClass('DIFF100')] p1: tolerance=0.127 checknetsindiffpair=TRUE checkdiffpairvsdiffpair=FALSE checkothers=FALSE
MatchedLengths DiffPair_DIFF90MatchedLengths [InDifferentialPairClass('DIFF90')] p2: tolerance=0.127 checknetsindiffpair=TRUE checkdiffpairvsdiffpair=FALSE checkothers=FALSE
MinimumSolderMaskSliver [All] p1: minsoldermaskwidth=0.1
PlaneClearance [All] p1: clearance=0.1
PlaneConnect [All] p1: planeconnectstyle=Direct reliefexpansion=0.508 reliefentries=4 reliefconductorwidth=0.254 reliefairgap=0.1
PolygonConnect [All] p1: connectstyle=Direct reliefconductorwidth=0.254 reliefentries=4 polygonreliefangle="90 Angle" airgapwidth=0.1
RoutingVias [All] p1: holewidth=0.2 width=0.45 viastyle="Through Hole" minholewidth=0.1 minwidth=0 maxholewidth=0.6 maxwidth=0.8
SilkToSilkClearance [All] p1: silktosilkclearance=0.1
SilkToSolderMaskClearance SilkscreenOverComponentPads [IsPad] p1: minsilkscreentomaskgap=0.1 clearancetoexposedcopper=TRUE
SolderMaskExpansion [All] p1: expansion=0.102
UnpouredPolygon [All] p1: allowunpoured=FALSE
Width DiffPair_DIFF100Width [InDifferentialPairClass('DIFF100')] p1: maxlimit=0.1 minlimit=0.085 preferedwidth=0.1 toplayer_minwidth=0.09 toplayer_maxwidth=0.09 toplayer_prefwidth=0.09 midlayer1_minwidth=0.1 midlayer2_maxwidth=0.085 midlayer2_prefwidth=0.085 midlayer3_minwidth=0.1 midlayer4_minwidth=0.1 midlayer5_maxwidth=0.085 midlayer5_prefwidth=0.085 midlayer6_minwidth=0.1 midlayer7_minwidth=0.1 midlayer8_minwidth=0.1 bottomlayer_minwidth=0.09 bottomlayer_maxwidth=0.09 bottomlayer_prefwidth=0.09 minimp=50.000000 maximp=50.000000 favimp=50.000000
Width DiffPair_DIFF90Width [InDifferentialPairClass('DIFF90')] p2: maxlimit=0.101 minlimit=0.085 preferedwidth=0.1 toplayer_minwidth=0.101 toplayer_prefwidth=0.101 midlayer1_minwidth=0.1 midlayer1_maxwidth=0.1 midlayer2_maxwidth=0.085 midlayer2_prefwidth=0.085 midlayer3_minwidth=0.1 midlayer3_maxwidth=0.1 midlayer4_minwidth=0.1 midlayer4_maxwidth=0.1 midlayer5_maxwidth=0.085 midlayer5_prefwidth=0.085 midlayer6_minwidth=0.1 midlayer6_maxwidth=0.1 midlayer7_minwidth=0.101 midlayer7_prefwidth=0.101 midlayer8_minwidth=0.101 midlayer8_prefwidth=0.101 bottomlayer_minwidth=0.101 bottomlayer_prefwidth=0.101 minimp=50.000000 maximp=50.000000 favimp=50.000000
Width "Width Ground" [InNet('GND')] p3: maxlimit=4 minlimit=0.2 preferedwidth=0.3
Width "Width Power" [InNet('+VIN') OR InNet('+1V2_ETH') OR InNet('+1V5_DDR') OR InNet('+1V375') OR InNet('+2V5') OR InNet('+3V3')] p4: maxlimit=4 minlimit=0.2 preferedwidth=0.3
Width [All] p5: maxlimit=4 minlimit=0.08 preferedwidth=0.1
20 further rules are at their usual default settings.

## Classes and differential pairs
net class RGMII_RXD: RGMII_R_RXCLK RGMII_RXCLK RGMII_RXD0 RGMII_RXD1 RGMII_RXD2 RGMII_RXD3 RGMII_RXDV
net class RGMII_MISC: RGMII_INT RGMII_INT_R RGMII_MDC RGMII_MDIO RGMII_R_MDC RGMII_R_MDIO
differential pair class DIFF100: CLK1 CLK1_C DRAM_CLK0 DRAM_CLK1 DRAM_DQS0 DRAM_DQS1 DRAM_DQS2 DRAM_DQS3 DRAM_DQS4 DRAM_DQS5 DRAM_DQS6 DRAM_DQS7 HDMI_CLK HDMI_D0 HDMI_D1 HDMI_D2 LVDS0_CLK LVDS0_TX0 LVDS0_TX1 LVDS0_TX2 LVDS0_TX3 SATA_C_RX SATA_C_TX SATA_RX SATA_TX TRD0 TRD1 TRD2 TRD3
differential pair class DIFF90: PCIE_C_TX PCIE_RX PCIE_TX USB0 USB1
net class SATA: SATA_C_RX_N SATA_C_RX_P SATA_C_TX_N SATA_C_TX_P SATA_REXT SATA_RX_N SATA_RX_P SATA_TX_N SATA_TX_P
net class DRAM_D[63..0]: DRAM_D0 DRAM_D1 DRAM_D2 DRAM_D3 DRAM_D4 DRAM_D5 DRAM_D6 DRAM_D7 DRAM_D8 DRAM_D9 DRAM_D10 DRAM_D11 DRAM_D12 DRAM_D13 DRAM_D14 DRAM_D15 DRAM_D16 DRAM_D17 DRAM_D18 DRAM_D19 DRAM_D20 DRAM_D21 DRAM_D22 DRAM_D23 DRAM_D24 DRAM_D25 DRAM_D26 DRAM_D27 DRAM_D28 DRAM_D29 DRAM_D30 DRAM_D31 DRAM_D32 DRAM_D33 DRAM_D34 DRAM_D35 DRAM_D36 DRAM_D37 DRAM_D38 DRAM_D39 DRAM_D40 DRAM_D41 DRAM_D42 DRAM_D43 DRAM_D44 DRAM_D45 DRAM_D46 DRAM_D47 DRAM_D48 DRAM_D49 DRAM_D50 DRAM_D51 DRAM_D52 DRAM_D53 DRAM_D54 DRAM_D55 DRAM_D56 DRAM_D57 DRAM_D58 DRAM_D59 DRAM_D60 DRAM_D61 DRAM_D62 DRAM_D63
net class USB1: USB1_N USB1_P USB1_PWR_EN
net class USB0: USB0_ID USB0_N USB0_P USB0_PWR_EN USB_OC
net class UART2: UART2_CTS UART2_RTS UART2_RXD UART2_TXD
net class UART1: UART1_CTS UART1_DCD UART1_DSR UART1_DTR UART1_RI UART1_RTS UART1_RXD UART1_TXD
net class SPI2: CSPI2_CLK CSPI2_CLK_R CSPI2_CS0 CSPI2_MISO CSPI2_MOSI
net class SPI3: CSPI3_CLK CSPI3_CLK_R CSPI3_CS2 CSPI3_MISO CSPI3_MOSI
net class MMC_CARD: SD2_ACT SD2_CD SD2_CLK SD2_CLK_R SD2_CMD SD2_CMD_R SD2_DATA0 SD2_DATA1 SD2_DATA2 SD2_DATA3 SD2_DATA4 SD2_DATA5 SD2_DATA6 SD2_DATA7 SD2_WP
net class RGMII_TXD: RGMII_R_TXCLK RGMII_TXCLK RGMII_TXD0 RGMII_TXD1 RGMII_TXD2 RGMII_TXD3 RGMII_TXEN
net class PCIE: CLK1_C_N CLK1_C_P CLK1_N CLK1_P PCIE_C_TX_N PCIE_C_TX_P PCIE_RX_N PCIE_RX_P PCIE_TX_N PCIE_TX_P PCIE_WAKE
net class SD_CARD: SD3_CD SD3_CLK SD3_CLK_R SD3_CMD SD3_CMD_R SD3_DATA0 SD3_DATA1 SD3_DATA2 SD3_DATA3 SD3_WP
net class LVDS: I2C3_SCL I2C3_SDA LVDS0_CABC LVDS0_CLK_N LVDS0_CLK_P LVDS0_PWM LVDS0_TX0_N LVDS0_TX0_P LVDS0_TX1_N LVDS0_TX1_P LVDS0_TX2_N LVDS0_TX2_P LVDS0_TX3_N LVDS0_TX3_P
net class JTAG: JTAG_MOD JTAG_NTRST JTAG_TCK JTAG_TCK_R JTAG_TDI JTAG_TDI_R JTAG_TDO JTAG_TDO_R JTAG_TMS
net class I2C: I2C4_SCL I2C4_SDA
net class HDMI: HDMI_CEC HDMI_CEC_IN HDMI_CLK_N HDMI_CLK_P HDMI_D0_N HDMI_D0_P HDMI_D1_N HDMI_D1_P HDMI_D2_N HDMI_D2_P HDMI_DDC HDMI_HPD I2C2_SCL I2C2_SDA
net class ENET: ENET_LED_LINK ENET_LED_RX ENET_REF_CLK ENET_REF_CLK_R ETH_ISET LED1 LED2 TRD0_N TRD0_P TRD1_N TRD1_P TRD2_N TRD2_P TRD3_N TRD3_P
net class DRAM_A[15..0]: DRAM_A0 DRAM_A1 DRAM_A2 DRAM_A3 DRAM_A4 DRAM_A5 DRAM_A6 DRAM_A7 DRAM_A8 DRAM_A9 DRAM_A10 DRAM_A11 DRAM_A12 DRAM_A13 DRAM_A14 DRAM_A15
net class DIFF100: CLK1_C_N CLK1_C_P CLK1_N CLK1_P DRAM_CLK0_N DRAM_CLK0_P DRAM_CLK1_N DRAM_CLK1_P DRAM_DQS0_N DRAM_DQS0_P DRAM_DQS1_N DRAM_DQS1_P DRAM_DQS2_N DRAM_DQS2_P DRAM_DQS3_N DRAM_DQS3_P DRAM_DQS4_N DRAM_DQS4_P DRAM_DQS5_N DRAM_DQS5_P DRAM_DQS6_N DRAM_DQS6_P DRAM_DQS7_N DRAM_DQS7_P HDMI_CLK_N HDMI_CLK_P HDMI_D0_N HDMI_D0_P HDMI_D1_N HDMI_D1_P HDMI_D2_N HDMI_D2_P LVDS0_CLK_N LVDS0_CLK_P LVDS0_TX0_N LVDS0_TX0_P LVDS0_TX1_N LVDS0_TX1_P LVDS0_TX2_N LVDS0_TX2_P LVDS0_TX3_N LVDS0_TX3_P SATA_C_RX_N SATA_C_RX_P SATA_C_TX_N SATA_C_TX_P SATA_RX_N SATA_RX_P SATA_TX_N SATA_TX_P TRD0_N TRD0_P TRD1_N TRD1_P TRD2_N TRD2_P TRD3_N TRD3_P
net class DIFF90: PCIE_C_TX_N PCIE_C_TX_P PCIE_RX_N PCIE_RX_P PCIE_TX_N PCIE_TX_P USB0_N USB0_P USB1_N USB1_P
net class Audio: AUD3_CLK AUD3_CLK_R AUD3_RXD AUD3_TXC AUD3_TXC_R AUD3_TXD AUD3_TXFS I2C1_SCL I2C1_SDA
component class "[17] - MECH": FID1 FID2 FID3 FID4 MH1 MH2 MH3 MH4 TP10
component class "[16] - PWR 2V5, 1V5": C223 C224 C225 C226 C227 C228 C229 C230 C231 C233 C234 C235 C236 C237 C238 L4 L5 Q6 Q7 R134 R135 R140 R141 R142 R145 R146 R147 R148 R149 R150 R151 R152 R153 R154 R155 R158 R163 R164 TP8 TP9 U13
component class "[15] - PWR 3V3, 1V375": C204 C205 C206 C207 C208 C209 C210 C211 C212 C213 C214 C215 C216 C217 C218 C219 C220 C221 C222 C232 L1 L2 L3 Q3 Q4 Q5 Q8 R93 R106 R107 R108 R116 R117 R118 R119 R120 R121 R122 R123 R124 R125 R126 R127 R128 R129 R130 R131 R132 R133 R136 R138 R139 TP6 TP7 TP11 U11 U12
component class "[14] - SPI FLASH, LEDS": C203 D2 D3 Q1 Q2 R109 R110 R113 R114 R115 U10
component class "[13] - ETHERNET PHY": C175 C176 C177 C178 C179 C180 C181 C182 C183 C184 C185 C186 C187 C188 C189 C190 C191 C192 C193 C194 C195 C196 C197 C198 C199 C200 C201 C202 C248 C249 FB3 FB4 FB5 FB6 FB7 FB8 R36 R75 R81 R82 R83 R84 R85 R86 R87 R89 R91 R94 R95 R96 R97 R98 R99 R101 R102 R162 TP5 U8 U9 Y3
component class "[11] - CPU - POWER": C90 C91 C92 C93 C94 C95 C96 C97 C98 C99 C100 C101 C102 C103 C104 C105 C106 C107 C108 C109 C110 C111 C112 C113 C114 C115 C116 C117 C118 C119 C120 C121 C122 C123 C124 C125 C126 C127 C128 C129 C130 C131 C132 C133 C134 C135 C136 C137 C138 C139 C140 C141 C142 C143 C144 C145 C146 C147 C148 C149 C150 C151 C152 C153 C154 C155 C156 C157 C158 C159 C160 C161 C162 C163 C164 C165 C166 C167 C168 C169 C170 C171 C172 C173 C174 FB2 R74 R76 R77 R78 R79 R80 R105
component class "[10] - CPU - JTAG, CONTROL": C83 C84 C85 C86 C87 C88 C89 D1 Q9 R37 R48 R49 R51 R53 R54 R55 R56 R57 R58 R59 R60 R61 R62 R63 R64 R65 R67 R68 R69 R70 R71 R73 R90 R92 R103 R104 R111 R137 R143 R144 R161 R165 TP3 U1 U6 U7 Y1 Y2
component class "[09] - CPU - UART, AUDIO": R46 R47 R72 R160
component class "[08] - CPU - SPI, I2C, SD, MMC": R1 R38 R39 R40 R41 R42 R43 R44 R45 R50 R52 R66 R112 R156 R157 R159
component class "[07] - CPU - USB, ETHERNET": C79 C80 C81 C82 R35 R88 R100
component class "[06] - CPU - HDMI, LVDS": C74 C75 C76 C77 C243 C246 C247 R21 R22 R23 R24 R25 R26 R27 R28 R29 R30 R31 R32 R33 R34
component class "[05] - CPU - PCIE, SATA": C61 C62 C63 C64 C65 C66 C67 C68 C69 C70 C71 C72 C73 C78 C244 C245 FB1 R13 R14 R15 R16 R17 R18 R19 R20
component class "[04] - CPU - DDR3, DDR3 MEM": C3 C4 C5 C6 C7 C8 C9 C10 C11 C12 C13 C14 C15 C16 C17 C18 C19 C20 C21 C22 C23 C24 C25 C26 C27 C28 C29 C30 C31 C32 C33 C34 C35 C36 C37 C38 C39 C40 C41 C42 C43 C44 C45 C46 C47 C48 C49 C50 C51 C52 C53 C54 C55 C56 C57 C58 C59 C60 R2 R3 R4 R5 R6 R7 R8 R9 R10 R11 R12 U2 U3 U4 U5
component class "[03] - CONNECTORS": C1 C2 C239 C240 C241 C242 J1 J2
net class DRAM_ADDR_CTRL: DRAM_A0 DRAM_A1 DRAM_A2 DRAM_A3 DRAM_A4 DRAM_A5 DRAM_A6 DRAM_A7 DRAM_A8 DRAM_A9 DRAM_A10 DRAM_A11 DRAM_A12 DRAM_A13 DRAM_A14 DRAM_A15 DRAM_CAS_B DRAM_CS0_B DRAM_RAS_B DRAM_RESET_B DRAM_SDBA0 DRAM_SDBA1 DRAM_SDBA2 DRAM_SDCKE0 DRAM_SDODT0 DRAM_WE_B
net class DRAM_BANK0: DRAM_D0 DRAM_D1 DRAM_D2 DRAM_D3 DRAM_D4 DRAM_D5 DRAM_D6 DRAM_D7 DRAM_DQM0 DRAM_DQS0_N DRAM_DQS0_P
net class DRAM_BANK1: DRAM_D8 DRAM_D9 DRAM_D10 DRAM_D11 DRAM_D12 DRAM_D13 DRAM_D14 DRAM_D15 DRAM_DQM1 DRAM_DQS1_N DRAM_DQS1_P
net class DRAM_BANK2: DRAM_D16 DRAM_D17 DRAM_D18 DRAM_D19 DRAM_D20 DRAM_D21 DRAM_D22 DRAM_D23 DRAM_DQM2 DRAM_DQS2_N DRAM_DQS2_P
net class DRAM_BANK3: DRAM_D24 DRAM_D25 DRAM_D26 DRAM_D27 DRAM_D28 DRAM_D29 DRAM_D30 DRAM_D31 DRAM_DQM3 DRAM_DQS3_N DRAM_DQS3_P
net class DRAM_BANK4: DRAM_D32 DRAM_D33 DRAM_D34 DRAM_D35 DRAM_D36 DRAM_D37 DRAM_D38 DRAM_D39 DRAM_DQM4 DRAM_DQS4_N DRAM_DQS4_P
net class DRAM_BANK5: DRAM_D40 DRAM_D41 DRAM_D42 DRAM_D43 DRAM_D44 DRAM_D45 DRAM_D46 DRAM_D47 DRAM_DQM5 DRAM_DQS5_N DRAM_DQS5_P
net class DRAM_BANK6: DRAM_D48 DRAM_D49 DRAM_D50 DRAM_D51 DRAM_D52 DRAM_D53 DRAM_D54 DRAM_D55 DRAM_DQM6 DRAM_DQS6_N DRAM_DQS6_P
net class DRAM_BANK7: DRAM_D56 DRAM_D57 DRAM_D58 DRAM_D59 DRAM_D60 DRAM_D61 DRAM_D62 DRAM_D63 DRAM_DQM7 DRAM_DQS7_N DRAM_DQS7_P
net class DRAM_SDCLK: DRAM_CLK0_N DRAM_CLK0_P DRAM_CLK1_N DRAM_CLK1_P
net class DRAM_OTHERS: ZQPAD
differential pair LVDS0_TX3: +LVDS0_TX3_P -LVDS0_TX3_N
differential pair SATA_TX: +SATA_TX_P -SATA_TX_N
differential pair SATA_RX: +SATA_RX_P -SATA_RX_N
differential pair PCIE_TX: +PCIE_TX_P -PCIE_TX_N
differential pair CLK1: +CLK1_P -CLK1_N
differential pair SATA_C_TX: +SATA_C_TX_P -SATA_C_TX_N
differential pair SATA_C_RX: +SATA_C_RX_P -SATA_C_RX_N
differential pair PCIE_RX: +PCIE_RX_P -PCIE_RX_N
differential pair PCIE_C_TX: +PCIE_C_TX_P -PCIE_C_TX_N
differential pair CLK1_C: +CLK1_C_P -CLK1_C_N
differential pair USB1: +USB1_P -USB1_N
differential pair USB0: +USB0_P -USB0_N
differential pair TRD3: +TRD3_P -TRD3_N
differential pair TRD2: +TRD2_P -TRD2_N
differential pair TRD1: +TRD1_P -TRD1_N
differential pair TRD0: +TRD0_P -TRD0_N
differential pair LVDS0_TX2: +LVDS0_TX2_P -LVDS0_TX2_N
differential pair LVDS0_TX1: +LVDS0_TX1_P -LVDS0_TX1_N
differential pair LVDS0_TX0: +LVDS0_TX0_P -LVDS0_TX0_N
differential pair LVDS0_CLK: +LVDS0_CLK_P -LVDS0_CLK_N
differential pair HDMI_D2: +HDMI_D2_P -HDMI_D2_N
differential pair HDMI_D1: +HDMI_D1_P -HDMI_D1_N
differential pair HDMI_D0: +HDMI_D0_P -HDMI_D0_N
differential pair HDMI_CLK: +HDMI_CLK_P -HDMI_CLK_N
differential pair DRAM_DQS0: +DRAM_DQS0_P -DRAM_DQS0_N
differential pair DRAM_DQS1: +DRAM_DQS1_P -DRAM_DQS1_N
differential pair DRAM_DQS2: +DRAM_DQS2_P -DRAM_DQS2_N
differential pair DRAM_DQS3: +DRAM_DQS3_P -DRAM_DQS3_N
differential pair DRAM_DQS4: +DRAM_DQS4_P -DRAM_DQS4_N
differential pair DRAM_DQS5: +DRAM_DQS5_P -DRAM_DQS5_N
differential pair DRAM_DQS6: +DRAM_DQS6_P -DRAM_DQS6_N
differential pair DRAM_DQS7: +DRAM_DQS7_P -DRAM_DQS7_N
differential pair DRAM_CLK0: +DRAM_CLK0_P -DRAM_CLK0_N
differential pair DRAM_CLK1: +DRAM_CLK1_P -DRAM_CLK1_N

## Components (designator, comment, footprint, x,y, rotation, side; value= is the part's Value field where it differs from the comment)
C1 "1u" C0402 24.2,9.8 r0 bottom
C2 "10uF" C1206 36.7,35.4 r0 top
C3 "220n" C0402 50.5,15.9 r180 top
C4 "220n" C0402 52.6,2.1 r180 top
C5 "220n" C0402 50.5,15.9 r180 bottom
C6 "220n" C0402 52.6,2.1 r180 bottom
C7 "100n" C0402 35.2,11.7 r0 bottom
C8 "220n" C0402 50.4,37.9 r180 top
C9 "220n" C0402 50.5,24.1 r180 top
C10 "220n" C0402 50.4,37.9 r180 bottom
C11 "220n" C0402 50.5,24.1 r180 bottom
C12 "22u" C0603 38.6,11.1 r270 top
C13 "22u" C0603 59.6,1.9 r0 top
C14 "22u" C0603 41,1.9 r180 top
C15 "22u" C0603 41,38.1 r180 top
C16 "22u" C0603 59.6,38.1 r0 top
C17 "22u" C0603 38.6,29 r90 top
C18 "100n" C0402 63.9,32.6 r270 bottom
C19 "10u" C0603 66.5,31.4 r270 bottom
C20 "100n" C0402 63.9,30.4 r270 bottom
C21 "220n" C0402 57,2.1 r0 top
C22 "220n" C0402 54.8,15.9 r0 top
C23 "220n" C0402 46.1,15.9 r180 top
C24 "220n" C0402 41.7,15.9 r180 top
C25 "220n" C0402 43.9,15.9 r180 top
C26 "220n" C0402 39.5,15.9 r180 top
C27 "220n" C0402 43.7,2.1 r0 top
C28 "220n" C0402 45.9,2.1 r180 top
C29 "220n" C0402 48.1,2.1 r180 top
C30 "220n" C0402 54.8,2.1 r0 top
C31 "220n" C0402 43.9,24.1 r180 top
C32 "220n" C0402 54.8,24.1 r0 top
C33 "220n" C0402 46.1,24.1 r180 top
C34 "220n" C0402 48.1,37.9 r180 top
C35 "220n" C0402 57,37.9 r0 top
C36 "220n" C0402 43.7,37.9 r180 top
C37 "220n" C0402 45.9,37.9 r180 top
C38 "220n" C0402 54.8,37.9 r0 top
C39 "220n" C0402 39.5,24.1 r180 top
C40 "220n" C0402 41.7,24.1 r180 top
C41 "220n" C0402 57,2.1 r0 bottom
C42 "220n" C0402 54.8,15.9 r0 bottom
C43 "220n" C0402 41.7,15.9 r180 bottom
C44 "220n" C0402 46.1,15.9 r180 bottom
C45 "220n" C0402 43.9,15.9 r180 bottom
C46 "220n" C0402 39.5,15.9 r180 bottom
C47 "220n" C0402 43.7,2.1 r0 bottom
C48 "220n" C0402 48.1,2.1 r180 bottom
C49 "220n" C0402 45.9,2.1 r180 bottom
C50 "220n" C0402 54.8,2.1 r0 bottom
C51 "220n" C0402 41.7,24.1 r180 bottom
C52 "220n" C0402 46.1,24.1 r180 bottom
C53 "220n" C0402 43.9,24.1 r180 bottom
C54 "220n" C0402 54.8,24.1 r0 bottom
C55 "220n" C0402 57,37.9 r0 bottom
C56 "220n" C0402 45.9,37.9 r180 bottom
C57 "220n" C0402 43.7,37.9 r180 bottom
C58 "220n" C0402 54.8,37.9 r0 bottom
C59 "220n" C0402 48.1,37.9 r180 bottom
C60 "220n" C0402 39.5,24.1 r180 bottom
C61 "220n" C0402 21.5,13.7 r270 bottom
C62 "220n" C0402 23.4,15.4 r0 bottom
C63 "100n" C0402 15.3,9.6 r270 top
C64 "220n" C0402 20.3,13.7 r270 bottom
C65 "100n" C0402 14.3,9.6 r270 top
C66 "100n" C0402 17.3,4.3 r0 top
C67 "100n" C0402 17.3,5.3 r0 top
C68 "220n" C0402 20.2,21.2 r180 bottom
C69 "10n" C0402 19.2,7.9 r270 top
C70 "10n" C0402 20.2,7.9 r270 top
C71 "10n" C0402 18,1.3 r0 top
C72 "10n" C0402 18,2.3 r0 top
C73 "220n" C0402 19.7,18.7 r270 bottom
C74 "100n" C0402 23.2,30.2 r0 bottom
C75 "220n" C0402 23.9,13.9 r270 bottom
C76 "220n" C0402 26.7,12.9 r270 bottom
C77 "220n" C0402 31.3,12.9 r270 bottom
C78 "4u7" C0402 19.4,11.3 r90 bottom
C79 "220n" C0402 18.6,16.4 r180 bottom
C80 "10u" C0603 16.6,14.6 r270 bottom
C81 "220n" C0402 19,15.4 r180 bottom
C82 "220n" C0402 16.8,17.4 r180 bottom
C83 "18p" C0402 14.2,15.3 r90 top
C84 "18p" C0402 14.2,12 r270 top
C85 "18p" C0402 15.1,20.7 r90 top
C86 "18p" C0402 13.9,20.7 r90 top
C87 "100n" C0402 66,7.3 r270 bottom
C88 "100n" C0402 61.4,7.3 r270 bottom
C89 "100n" C0402 5.9,7.3 r90 bottom
C90 "220n" C0402 25.5,15.9 r270 bottom
C91 "220n" C0402 25.6,17.4 r0 bottom
C92 "220n" C0402 22.1,20.8 r90 bottom
C93 "220n" C0402 23.7,20.9 r90 bottom
C94 "220n" C0402 25.3,20.9 r270 bottom
C95 "220n" C0402 26.9,21.1 r90 bottom
C96 "22u" C0603 30.1,12.9 r270 bottom
C97 "220n" C0402 28.3,21.1 r90 bottom
C98 "220n" C0402 20.2,20.2 r180 bottom
C99 "220n" C0402 25.3,18.9 r270 bottom
C100 "220n" C0402 23.4,17.4 r0 bottom
C101 "22u" C0603 17.4,19.8 r180 bottom
C102 "220n" C0402 29.8,18.6 r0 bottom
C103 "220n" C0402 21.9,18.8 r270 bottom
C104 "220n" C0402 23.9,18.9 r270 bottom
C105 "220n" C0402 28.3,19.1 r90 bottom
C106 "22u" C0603 30.1,16.7 r270 bottom
C107 "220n" C0402 26.7,15.1 r270 bottom
C108 "220n" C0402 27.7,15.1 r270 bottom
C109 "220n" C0402 28.7,15.1 r270 bottom
C110 "220n" C0402 30.3,14.8 r0 bottom
C111 "22u" C0603 17.4,21.2 r180 bottom
C112 "220n" C0402 30.4,19.6 r0 bottom
C113 "220n" C0402 28.2,22.6 r180 bottom
C114 "220n" C0402 29.9,22.5 r90 bottom
C115 "220n" C0402 28.3,17.1 r270 bottom
C116 "220n" C0402 27.1,17.1 r270 bottom
C117 "220n" C0402 30.3,21 r0 bottom
C118 "22u" C0603 32.9,21.2 r0 bottom
C119 "220n" C0402 28.2,25 r0 bottom
C120 "220n" C0402 26.7,23.1 r90 bottom
C121 "220n" C0402 28.2,23.6 r180 bottom
C122 "220n" C0402 21.9,24.9 r90 bottom
C123 "220n" C0402 23.7,22.9 r270 bottom
C124 "220n" C0402 25.3,22.9 r270 bottom
C125 "220n" C0402 21.2,26.5 r0 bottom
C126 "220n" C0402 22.1,22.8 r270 bottom
C127 "22u" C0603 20.6,28.8 r0 bottom
C128 "22u" C0603 16.2,25.7 r270 bottom
C129 "22u" C0603 28.5,27 r90 bottom
C130 "220n" C0402 26.7,25.1 r90 bottom
C131 "220n" C0402 22.9,25.7 r90 bottom
C132 "220n" C0402 21.2,27.5 r180 bottom
C133 "220n" C0402 25.3,24.9 r90 bottom
C134 "220n" C0402 23.9,24.9 r90 bottom
C135 "22u" C0603 22.9,28.3 r90 bottom
C136 "220n" C0402 23.4,16.4 r0 bottom
C137 "22u" C0805 14.8,19.8 r90 bottom
C138 "220n" C0402 26.9,19.1 r270 bottom
C139 "10n" C0402 21,17 r0 bottom
C140 "220n" C0402 18.3,18 r90 bottom
C141 "22u" C0805 14.7,15.8 r270 bottom
C142 "220n" C0402 20.7,18.5 r270 bottom
C143 "220n" C0402 21,15.4 r180 bottom
C144 "220n" C0402 26.2,27.1 r90 bottom
C145 "220n" C0402 27.9,12.9 r270 bottom
C146 "220n" C0402 25.2,27.1 r90 bottom
C147 "22u" C0805 31,10.4 r0 bottom
C148 "22u" C0805 16.8,28.9 r90 bottom
C149 "220n" C0402 25.1,13.9 r270 bottom
C150 "220n" C0402 19.1,13.9 r270 bottom
C151 "22u" C0603 17.5,12.2 r180 bottom
C152 "220n" C0402 20.1,25.4 r180 bottom
C153 "220n" C0402 17.4,24.9 r90 bottom
C154 "220n" C0402 20.2,23.2 r180 bottom
C155 "220n" C0402 27.2,27.1 r90 bottom
C156 "22u" C0805 27.5,29.5 r180 bottom
C157 "220n" C0402 30.9,24.1 r90 bottom
C158 "220n" C0402 32.1,16.6 r0 bottom
C159 "220n" C0402 29.9,24.7 r90 bottom
C160 "220n" C0402 29.9,27.1 r90 bottom
C161 "220n" C0402 31.9,15.1 r270 bottom
C162 "220n" C0402 32.1,17.8 r0 bottom
C163 "220n" C0402 28.9,12.9 r270 bottom
C164 "220n" C0402 20.2,22.2 r180 bottom
C165 "220n" C0402 20.1,24.2 r180 bottom
C166 "220n" C0402 24.2,27.1 r90 bottom
C167 "220n" C0402 31.4,25.9 r0 bottom
C168 "220n" C0402 31.5,22.6 r0 bottom
C169 "220n" C0402 32.4,18.8 r0 bottom
C170 "220n" C0402 32.4,19.8 r0 bottom
C171 "220n" C0402 33.5,22.9 r0 bottom
C172 "22u" C0603 35.7,19.6 r0 bottom
C173 "22u" C0603 31.8,27.1 r0 bottom
C174 "220n" C0402 22.7,13.7 r270 bottom
C175 "22pF" C0402 14.4,30.2 r0 bottom
C176 "22pF" C0402 12.2,30.2 r180 bottom
C177 "10u" C0603 2.4,29.6 r0 bottom
C178 "10u" C0603 5,34 r90 bottom
C179 "560pF" C0402 4.8,31.4 r270 bottom
C180 "10u" C0603 6.7,37.7 r180 bottom
C181 "100n" C0402 6.6,39 r180 bottom
C182 "10n" C0402 10.7,31.9 r90 bottom
C183 "10n" C0402 9.4,35.1 r0 bottom
C184 "10n" C0402 8.9,37.3 r90 bottom
C185 "10n" C0402 15.3,38.2 r270 bottom
C186 "10u" C0603 13.1,35.4 r180 bottom
C187 "100n" C0402 15.8,35.7 r180 bottom
C188 "10n" C0402 15.8,34.4 r180 bottom
C189 "10n" C0402 15.8,36.7 r180 bottom
C190 "100n" C0402 16,31.9 r90 bottom
C191 "10u" C0603 13.1,34 r0 bottom
C192 "100n" C0402 14,32 r90 bottom
C193 "10n" C0402 12.7,32 r90 bottom
C194 "10u" C0603 9.1,33.8 r0 bottom
C195 "100n" C0402 9.2,31.5 r0 bottom
C196 "10n" C0402 14.2,38.2 r270 bottom
C197 "10n" C0402 9.2,32.5 r0 bottom
C198 "10n" C0402 11.7,32 r90 bottom
C199 "10u" C0603 20.6,30.2 r0 bottom
C200 "10n" C0402 15.8,33.4 r180 bottom
C201 "10n" C0402 16.3,38.2 r270 bottom
C202 "10n" C0402 15,31.9 r90 bottom
C203 "100n" C0402 29.3,7.7 r270 top
C204 "10u" C0603 8.5,15.4 r270 bottom
C205 "100n" C0402 9.4,17.6 r0 bottom
C206 "1u" C0402 1.3,20.1 r90 bottom
C207 "1u" C0402 10.4,22 r0 bottom
C208 "1uF" C0805 10.7,19.2 r0 bottom
C209 "10uF" C1206 6.5,2.6 r270 top
C210 "10uF" C1206 6.5,37.3 r90 top
C211 "100n" C0402 1.9,16.4 r180 bottom
C212 "100n" C0402 1.8,23.8 r0 bottom
C213 "100µF" C1206 11.3,13.9 r0 top
C214 "100µF" C1206 11.3,16.4 r0 top
C215 "100µF" C1206 11.3,11.4 r0 top
C216 "100µF" C1206 6.7,20 r270 top
C217 "100µF" C1206 4.2,20 r270 top
C218 "10n" C0402 10.4,20.9 r0 bottom
C219 "100n" C0402 9.9,23.5 r0 bottom
C220 "10uF" C1206 10.1,9 r180 top
C221 "10u" C0603 13.3,6.3 r90 top
C222 "10u" C0603 14.9,6.3 r90 top
C223 "10u" C0603 59.6,23.7 r180 bottom
C224 "100n" C0402 61.6,24 r90 bottom
C225 "1u" C0402 68.5,20 r270 bottom
C226 "1u" C0402 60.2,18.5 r180 bottom
C227 "1uF" C0805 59.3,21.7 r180 bottom
C228 "10uF" C1206 63.5,37.4 r90 top
C229 "10uF" C1206 63.5,2.6 r270 top
C230 "100n" C0402 68,24.6 r0 bottom
C231 "100n" C0402 68.2,16.1 r180 bottom
C232 "100µF" C1206 10.1,20 r270 top
C233 "100µF" C1206 58.6,21.2 r180 top
C234 "100µF" C1206 64.1,21.1 r0 top
C235 "100µF" C1206 64.1,18.9 r0 top
C236 "100µF" C1206 58.6,18.7 r180 top
C237 "10n" C0402 60.2,20 r180 bottom
C238 "100n" C0402 60.2,17.3 r180 bottom
C239 "100n" C0402 33.9,36.9 r270 top
C240 "100n" C0402 33.9,34.9 r90 top
C241 "10uF" C1206 36.7,32.8 r0 top
C242 "100n" C0402 30.6,35.2 r270 top
C243 "4u7" C0402 33,12.6 r0 bottom
C244 "4u7" C0402 16.3,10 r90 bottom
C245 "4u7" C0402 35.2,10.6 r0 bottom
C246 "4u7" C0402 15,22.4 r180 bottom
C247 "4u7" C0402 15,23.4 r180 bottom
C248 "10n" C0402 13.2,38.2 r270 bottom
C249 "10n" C0402 11,38.7 r0 bottom
D1 "RB751V-40-TP" SOD323 8.5,8.1 r180 bottom
D2 "Green" LED_0603 8.7,2.1 r90 top
D3 "Orange" LED_0603 27.7,1.9 r270 top
FB1 "220R, 2.5A" C0603 21.4,10 r0 bottom
FB2 "220R, 2.5A" C0603 18.5,29.9 r90 bottom
FB3 "BLM18KG101TN1D" C0603 6.7,36.1 r180 bottom
FB4 "BLM18KG101TN1D" C0603 11,37 r0 bottom
FB5 "BLM15AX601SN1D" C0402 11.1,34.6 r270 bottom
FB6 "BLM18KG101TN1D" C0603 6.9,28.2 r90 bottom
FB7 "BLM18KG101TN1D" C0603 19.9,31.8 r180 top
FB8 "220R, 2.5A" C0603 6,31.2 r270 bottom
FID1 "FID_1MM_SMALL" FID_40X52D 57.5,0.8 r90 top
FID2 "FID_1MM_SMALL" FID_40X52D 64,2.5 r90 bottom
FID3 "FID_1MM_SMALL" FID_40X52D 17,39 r90 top
FID4 "FID_1MM_SMALL" FID_40X52D 1,27 r90 bottom
J1 "QSH-030-01-L-D-A" QSH-030-01-L-D-A 28,35.2 r90 bottom locked
J2 "QSH-030-01-L-D-A" QSH-030-01-L-D-A 28,4.8 r90 bottom locked
L1 "4µ7" IHLP_255MILX270MIL 5,14 r180 top locked
L2 "3u3" IHLP_255MILX270MIL 5,26 r270 top locked
L3 "VLCF4020T-100MR85" VLCF4020 12.3,2.5 r0 top locked
L4 "3u3" IHLP_255MILX270MIL 65,26 r0 top locked
L5 "3u3" IHLP_255MILX270MIL 65,14 r180 top locked
MH1 "MH_5MMC_2.2MMD" MH_5MMD_2.2MMD 67.5,37.5 r0 top locked
MH2 "MH_5MMC_2.2MMD" MH_5MMD_2.2MMD 67.5,2.5 r0 top locked
MH3 "MH_5MMC_2.2MMD" MH_5MMD_2.2MMD 2.5,2.5 r0 top locked
MH4 "MH_5MMC_2.2MMD" MH_5MMD_2.2MMD 2.5,37.5 r0 top locked
Q1 "2N7002BKW,115" SC70_SOT323 8.6,2.3 r0 bottom
Q2 "2N7002BKW,115" SC70_SOT323 29.9,2.8 r270 top
Q3 "SI4816BDY-T1-GE3" 8_SOIC_3.9MM 4.2,7.7 r180 top locked
Q4 "SI4816BDY-T1-GE3" 8_SOIC_3.9MM 4.2,32.3 r0 top locked
Q5 "2N7002BKW,115" SC70_SOT323 2.7,14.6 r0 bottom
Q6 "SI4816BDY-T1-GE3" 8_SOIC_3.9MM 65.8,32.3 r0 top locked
Q7 "SI4816BDY-T1-GE3" 8_SOIC_3.9MM 65.8,7.7 r180 top locked
Q8 "2N7002BKW,115" SC70_SOT323 2.7,11.9 r0 bottom
Q9 "2N7002BKW,115" SC70_SOT323 12.7,2.3 r180 bottom
R1 "22R" R0402 12.4,22.9 r90 top
R2 "200R" R0402 52.6,38 r0 bottom
R3 "200R" R0402 50.4,2 r0 top
R4 "240R" R0402 52.7,16 r180 top
R5 "240R" R0402 50.4,2 r0 bottom
R6 "10k" R0402 38.2,18 r270 top
R7 "10k" R0402 33.5,14.1 r180 bottom
R8 "240R" R0402 52.6,38 r180 top
R9 "240R" R0402 52.7,24 r180 bottom
R10 "240R" R0402 37.9,23.6 r90 top
R11 "240R" R0402 65.2,32.6 r90 bottom
R12 "240R" R0402 65.2,30.4 r90 bottom
R13 "0R" R0402 20.6,11.7 r90 bottom
R14 "0R" R0402 17.8,10.1 r0 bottom
R15 "200R" R0402 15.2,10 r90 bottom
R16 "49R9" R0402 18.9,5.8 r270 top
R17 "49R9" R0402 18.9,3.8 r90 top
R18 "0R" R0402 16.6,22.9 r90 bottom
R19 "0R" R0402 16.8,18.5 r0 bottom
R20 "191R" R0402 18.2,22.7 r180 bottom
R21 "47k" R0402 24.8,31.7 r0 top
R22 "47k" R0402 29.6,33 r0 top
R23 "0R" R0402 24.8,11.9 r90 bottom
R24 "0R" R0402 24.9,35.2 r90 top
R25 "0R" R0402 27.5,35.2 r90 top
R26 "0R" R0402 23.5,35.2 r270 top
R27 "0R" R0402 27.4,10.4 r90 bottom
R28 "4k99" R0402 26.8,38.5 r180 top
R29 "4k99" R0402 26.8,37.3 r180 top
R30 "1k6" R0402 23.6,11.3 r270 bottom
R31 "4k99" R0402 34,2.7 r180 top
R32 "4k99" R0402 33.987,1.408 r180 top
R33 "10k" R0402 35,4.6 r270 top
R34 "0R" R0402 33.4,11.1 r90 bottom
R35 "22R" R0402 18.9,27.1 r90 bottom
R36 "22R" R0402 12.4,27.2 r270 top
R37 "2M2" R0402 15.3,15.3 r90 top
R38 "10k" R0402 29.6,31.7 r0 top
R39 "10k" R0402 29.2,38.5 r0 top
R40 "10k" R0402 29.2,35.2 r90 top
R41 "10k" R0402 10.4,5.6 r0 bottom
R42 "10k" R0402 11.8,7.1 r180 bottom
R43 "10k" R0402 11.8,8.3 r180 bottom
R44 "4k99" R0402 27.2,31.7 r180 top
R45 "4k99" R0402 27.2,32.9 r180 top
R46 "4k99" R0402 35.6,7 r0 top
R47 "4k99" R0402 35.6,8.2 r0 top
R48 "10k" R0402 5.4,9.5 r270 bottom
R49 "10k" R0402 32.075,31.67 r180 top
R50 "22R" R0402 12.4,20.7 r90 top
R51 "0R" R0402 32.075,32.97 r0 top
R52 "22R" R0402 14.2,25 r270 bottom
R53 "10M" R0402 15.3,13.3 r270 top
R54 "10M" R0402 14.7,16.9 r180 top
R55 "4k99" R0402 7.5,13.1 r180 bottom
R56 "4k99" R0402 8.2,9.4 r180 bottom
R57 "10k" R0402 7.5,10.7 r180 bottom
R58 "10k" R0402 12.1,5.2 r270 bottom
R59 "4k99" R0402 61.4,9.7 r270 bottom
R60 "10k" R0402 61.7,2.5 r270 bottom
R61 "1k" R0402 22,11.7 r90 bottom
R62 "10k" R0402 25.8,2.6 r0 top
R63 "10k" R0402 21.1,1.4 r180 top
R64 "10k" R0402 21.1,2.6 r180 top
R65 "0R" R0402 14.1,30 r180 top
R66 "22R" R0402 12.8,25 r270 bottom
R67 "10k" R0402 63.8,10.2 r180 bottom
R68 "10k" R0402 1.4,9.5 r90 bottom
R69 "10k" R0402 2.8,9.5 r90 bottom
R70 "0R" R0402 8,6.8 r180 bottom
R71 "0R" R0402 4.2,9.5 r270 bottom
R72 "22R" R0402 32.712,6.985 r0 top
R73 "100k" R0402 5.3,11.3 r0 bottom
R74 "0R" R0402 30,29.1 r90 bottom
R75 "10k" R0402 14.1,28.8 r180 top
R76 "0R" R0402 28.6,10.4 r270 bottom
R77 "2R2" R0402 14,10 r90 bottom
R78 "0R" R0402 26,10.4 r270 bottom
R79 "10R" R0402 14.3,12.2 r270 bottom
R80 "0R" R0402 18.5,24.9 r270 bottom
R81 "220R" R0402 24.7,38.5 r180 top
R82 "220R" R0402 22,38.5 r0 top
R83 "22R" R0402 7.7,30.3 r180 bottom
R84 "4k99" R0402 17.5,31.6 r0 top
R85 "22R" R0402 9.6,29.2 r90 top
R86 "22R" R0402 11,27.2 r90 top
R87 "4k99" R0402 9.6,27.2 r270 top
R88 "0R" R0402 12.4,25.2 r90 top
R89 "4k99" R0402 11,29.2 r90 top
R90 "22R" R0402 23.4,2.6 r0 top
R91 "10k" R0402 14.1,22.5 r180 top
R92 "22R" R0402 25.8,1.4 r180 top
R93 "0R" R0402 8,5.6 r180 bottom
R94 "10k" R0402 20.025,38.5 r180 top
R95 "10k" R0402 14.1,27.6 r180 top
R96 "10k" R0402 14.1,25.1 r180 top
R97 "10k" R0402 14.1,23.7 r180 top
R98 "10k" R0402 14.1,26.4 r180 top
R99 "1k" R0402 12.4,29.2 r90 top
R100 "10k" R0402 29.2,37.3 r0 top
R101 "1k" R0402 7.4,31.9 r90 bottom
R102 "1k" R0402 24.7,37.3 r0 top
R103 "10k" R0402 7.5,11.9 r180 bottom
R104 "10k" R0402 13.4,5.2 r90 bottom
R105 "0R" R0402 15.5,12.2 r90 bottom
R106 "0R" R0402 10.4,4.2 r180 bottom
R107 "0R" R0402 6,2.2 r90 bottom
R108 "0R" R0402 4.8,24.3 r270 bottom
R109 "10k" R0402 30.4,7.7 r270 top
R110 "10k" R0402 21.3,7.9 r90 top
R111 "100k" R0402 22.3,31.7 r180 top
R112 "22R" R0402 24.675,29.075 r180 bottom
R113 "220R" R0402 8,4.4 r180 bottom
R114 "220R" R0402 32.1,1.9 r90 top
R115 "10k" R0402 32,4.5 r270 top
R116 "0R" R0402 13.2,19.2 r270 bottom
R117 "0R" R0402 12.6,21.2 r0 bottom
R118 "10R" R0402 13.4,22.9 r90 bottom
R119 "14K" R0402 7.25,26 r0 bottom
R120 "4k99" R0402 7.8,24.6 r180 bottom
R121 "1R" R0402 1.4,22.2 r90 bottom
R122 "1R" R0402 1.5,17.9 r90 bottom
R123 "39k" R0402 6.5,16.4 r0 bottom
R124 "200k" R0402 6.2,24.3 r90 bottom
R125 "200k" R0402 4.9,15.5 r90 bottom
R126 "10k5" R0402 6.5,15.1 r0 bottom
R127 "10k" R0402 12.2,22.9 r90 bottom
R128 "0R" R0402 11.5,25 r270 bottom
R129 "10k" R0402 6,4.4 r0 bottom
R130 "10k" R0402 3.4,24.8 r90 bottom
R131 "10k" R0402 5.3,12.7 r0 bottom
R132 "10k" R0402 5.3,13.9 r0 bottom
R133 "10k" R0402 9.9,25 r180 bottom
R134 "12k" R0402 61.7,14.6 r180 bottom
R135 "3k3" R0402 61.7,15.9 r180 bottom
R136 "10k" R0402 5.2,26 r0 bottom
R137 "100k" R0402 24.8,32.9 r0 top
R138 "330k" R0402 8.6,4.8 r270 top
R139 "120k" R0402 8.6,6.8 r270 top
R140 "0R" R0402 56.8,21.7 r90 bottom
R141 "0R" R0402 56.9,19.1 r270 bottom
R142 "10R" R0402 56.4,16.4 r270 bottom
R143 "100k" R0402 22.3,32.9 r0 top
R144 "100k" R0402 26.1,35.2 r270 top
R145 "1R" R0402 68.4,23 r270 bottom
R146 "1R" R0402 68.6,17.8 r270 bottom
R147 "27k" R0402 63.2,24 r180 bottom
R148 "200k" R0402 63.5,15.5 r270 bottom
R149 "200k" R0402 64.9,24.4 r270 bottom
R150 "10k5" R0402 63.2,25.4 r0 bottom
R151 "10k" R0402 58.2,19.1 r270 bottom
R152 "0R" R0402 57.9,16.4 r90 bottom
R153 "10k" R0402 65.3,26.1 r180 bottom
R154 "10k" R0402 66.1,15.5 r270 bottom
R155 "10k" R0402 59.5,16 r180 bottom
R156 "0R" R0402 36.187,1.408 r180 top
R157 "0R" R0402 36.2,2.7 r180 top
R158 "10k" R0402 61.7,13.2 r0 bottom
R159 "22R" R0402 32,28.4 r0 bottom
R160 "22R" R0402 32.712,8.172 r0 top
R161 "22R" R0402 23.4,1.4 r0 top
R162 "1k" R0402 11,25.2 r270 top
R163 "0R" R0402 66.2,24.4 r270 bottom
R164 "0R" R0402 64.9,15.5 r90 bottom
R165 "10k" R0402 14.8,5.2 r90 bottom
TP3 "TP_25MILC" TP_25C 12.8,17.2 r90 bottom
TP5 "TP_25MILC" TP_25C 7,33.9 r90 bottom
TP6 "TP_25MILC" TP_25C 8.4,19.3 r90 top
TP7 "TP_25MILC" TP_25C 9.4,22.9 r90 top
TP8 "TP_25MILC" TP_25C 60.6,22.9 r90 top
TP9 "TP_25MILC" TP_25C 60,17 r90 top
TP10 "TP_25MILC" TP_25C 56.8,22.9 r90 top
TP11 "TP_25MILC" TP_25C 15.2,2.4 r90 top
U1 "MCIMX6Q5EYM10AC" PBGA624 26.5,20 r90 top locked
U2 "MT41J128M16HA-15E:D TR" 96_FPGA_DD3 50,9 r90 top locked
U3 "MT41J128M16HA-15E:D TR" 96_FPGA_DD3 50,9 r270 bottom locked
U4 "MT41J128M16HA-15E:D TR" 96_FPGA_DD3 50,31 r90 top locked
U5 "MT41J128M16HA-15E:D TR" 96_FPGA_DD3 50,31 r270 bottom locked
U6 "TPS3808G09DBVRG4" DBV_SOT_23_6 63.7,7.4 r90 bottom locked
U7 "SN74AHC1G09DBVR" DBV_SOT_23_5 3.3,6.8 r0 bottom
U8 "KSZ9021RN" QFN48_7MMX7MM 12.5,35 r180 top locked
U9 "MIC33050-4YHL TR" MLF_3X3_12PINS 2.5,32.2 r0 bottom locked
U10 "SST25VF016B-75-4I-QAF-ND" WSON8_6X5MM 25.3,6.4 r0 top locked
U11 "ISL6236AIRZ" 32_VFQFN_EXPOSED_PAD 5.3,20 r180 bottom locked
U12 "TPS62175DQCT" DQC_PWSON-N10 10.9,6.4 r270 top locked
U13 "ISL6236AIRZ" 32_VFQFN_EXPOSED_PAD 64.7,20 r0 bottom
Y1 "24MHz" ABM7_V1_1 11.6,13.2 r270 bottom
Y2 "32.768kHz" ABS06 14.2,18.7 r180 top
Y3 "25MHz" ABM7_V1_1 11.75,27.85 r0 bottom

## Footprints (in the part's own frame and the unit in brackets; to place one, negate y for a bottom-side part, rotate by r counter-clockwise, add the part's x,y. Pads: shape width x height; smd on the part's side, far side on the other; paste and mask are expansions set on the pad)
8_SOIC_3.9MM [mm]
  rect 1.2x0.58 smd: 1(-2.8,1.905) 2(-2.8,0.635) 3(-2.8,-0.635) 4(-2.8,-1.905) 5(2.8,-1.905) 6(2.8,-0.635) 7(2.8,0.635) 8(2.8,1.905)
  silkscreen extent -1.91,-2.54 1.91,2.54, body extent -3,-2.45 3,2.45, height 1.75
32_VFQFN_EXPOSED_PAD [mm]
  rect 0.6x0.23 smd mask+0.051: 1(-2.4,1.75) 2(-2.4,1.25) 3(-2.4,0.75) 4(-2.4,0.25) 5(-2.4,-0.25) 6(-2.4,-0.75) 7(-2.4,-1.25) 8(-2.4,-1.75) 17(2.4,-1.75) 18(2.4,-1.25) 19(2.4,-0.75) 20(2.4,-0.25) 21(2.4,0.25) 22(2.4,0.75) 23(2.4,1.25) 24(2.4,1.75)
  rect 0.23x0.6 smd mask+0.051: 9(-1.75,-2.4) 10(-1.25,-2.4) 11(-0.75,-2.4) 12(-0.25,-2.4) 13(0.25,-2.4) 14(0.75,-2.4) 15(1.25,-2.4) 16(1.75,-2.4) 25(1.75,2.4) 26(1.25,2.4) 27(0.75,2.4) 28(0.25,2.4) 29(-0.25,2.4) 30(-0.75,2.4) 31(-1.25,2.4) 32(-1.75,2.4)
  rect 3.3x3.3 smd paste-10 mask+0.051: 33(0,0)
  silkscreen extent -2.7,-2.54 2.54,2.88, body extent -2.54,-2.54 2.54,2.54, height 0.9
96_FPGA_DD3 [mm]
  round 0.35 smd mask+0.05: A1(-3.2,6) A2(-2.4,6) A3(-1.6,6) A7(1.6,6) A8(2.4,6) A9(3.2,6) B1(-3.2,5.2) B2(-2.4,5.2) B3(-1.6,5.2) B7(1.6,5.2) B8(2.4,5.2) B9(3.2,5.2) C1(-3.2,4.4) C2(-2.4,4.4) C3(-1.6,4.4) C7(1.6,4.4) C8(2.4,4.4) C9(3.2,4.4) D1(-3.2,3.6) D2(-2.4,3.6) D3(-1.6,3.6) D7(1.6,3.6) D8(2.4,3.6) D9(3.2,3.6) E1(-3.2,2.8) E2(-2.4,2.8) E3(-1.6,2.8) E7(1.6,2.8) E8(2.4,2.8) E9(3.2,2.8) F1(-3.2,2) F2(-2.4,2) F3(-1.6,2) F7(1.6,2) F8(2.4,2) F9(3.2,2) G1(-3.2,1.2) G2(-2.4,1.2) G3(-1.6,1.2) G7(1.6,1.2) G8(2.4,1.2) G9(3.2,1.2) H1(-3.2,0.4) H2(-2.4,0.4) H3(-1.6,0.4) H7(1.6,0.4) H8(2.4,0.4) H9(3.2,0.4) J1(-3.2,-0.4) J2(-2.4,-0.4) J3(-1.6,-0.4) J7(1.6,-0.4) J8(2.4,-0.4) J9(3.2,-0.4) K1(-3.2,-1.2) K2(-2.4,-1.2) K3(-1.6,-1.2) K7(1.6,-1.2) K8(2.4,-1.2) K9(3.2,-1.2) L1(-3.2,-2) L2(-2.4,-2) L3(-1.6,-2) L7(1.6,-2) L8(2.4,-2) L9(3.2,-2) M1(-3.2,-2.8) M2(-2.4,-2.8) M3(-1.6,-2.8) M7(1.6,-2.8) M8(2.4,-2.8) M9(3.2,-2.8) MECH01(-4,8.4) MECH02(-3.2,8.4) MECH03(-1.6,8.4) MECH04(1.6,8.4) MECH05(3.2,8.4) MECH06(4,8.4) MECH07(-4,6) MECH08(4,6) MECH09(-4,-6) MECH10(4,-6) MECH11(-4,-8.4) MECH12(-3.2,-8.4) MECH13(-1.6,-8.4) MECH14(1.6,-8.4) MECH15(3.2,-8.4) MECH16(4,-8.4) N1(-3.2,-3.6) N2(-2.4,-3.6) N3(-1.6,-3.6) N7(1.6,-3.6) N8(2.4,-3.6) N9(3.2,-3.6) P1(-3.2,-4.4) P2(-2.4,-4.4) P3(-1.6,-4.4) P7(1.6,-4.4) P8(2.4,-4.4) P9(3.2,-4.4) R1(-3.2,-5.2) R2(-2.4,-5.2) R3(-1.6,-5.2) R7(1.6,-5.2) R8(2.4,-5.2) R9(3.2,-5.2) T1(-3.2,-6) T2(-2.4,-6) T3(-1.6,-6) T7(1.6,-6) T8(2.4,-6) T9(3.2,-6)
  silkscreen extent -6.15,-10.5 6.15,10.5, body extent -6.16,-10.54 6.16,10.54, height 1.2
ABM7_V1_1 [mm] "Corrected from 2.2 to 2.4 between pads"
  rect 1.9x2.6 smd: 1(-2.15,0) 2(2.15,0)
  silkscreen extent -3.4,-1.8 3.4,1.8, body extent -3.1,-1.85 3.1,1.85, height 1.45
ABS06 [mm]
  rect 0.75x1.4 smd: 1(-0.725,0) 2(0.725,0)
  silkscreen extent -1.4,-1 1.4,1, body extent -1,-0.62 1,0.6, height 1
C0402 [mm]
  rect 0.5x0.5 smd: 1(-0.5,0) 2(0.5,0)
  silkscreen extent -1,-0.5 1,0.5, body extent -0.5,-0.25 0.5,0.25, height 0.56
C0603 [mm]
  rect 0.8x0.8 smd: 1(-0.75,0) 2(0.75,0)
  silkscreen extent -1.4,-0.7 1.4,0.7, body extent -0.8,-0.42 0.8,0.44, height 0.95
C0805 [mm]
  rect 0.9x1.3 smd: 1(-0.95,0) 2(0.95,0)
  silkscreen extent -1.78,-1.02 1.78,1.02, body extent -1,-0.6 1,0.6, height 1.5
C1206 [mm]
  rect 0.9x1.6 smd: 1(-1.55,0) 2(1.55,0)
  silkscreen extent -2.29,-1.14 2.29,1.14, body extent -1.6,-0.8 1.6,0.8, height 1.8
DBV_SOT_23_5 [mm]
  rect 1x0.55 smd: 1(-1.35,0.95) 2(-1.35,0) 3(-1.35,-0.95) 4(1.35,-0.95) 5(1.35,0.95)
  silkscreen extent -0.9,-1.59 1.02,1.59, body extent -1.5,-1.5 1.5,1.5, height 1.45
DBV_SOT_23_6 [mm]
  rect 1x0.55 smd: 1(-1.35,0.95) 2(-1.35,0) 3(-1.35,-0.95) 4(1.35,-0.95) 5(1.35,0) 6(1.35,0.95)
  silkscreen extent -1.75,-1.59 0.9,1.8, body extent -1.59,-1.59 1.59,1.59, height 1.45
DQC_PWSON-N10 [mm] "Creator MM"
  rect 0.5x0.25 smd mask+0.07: 1(-0.95,1) 2(-0.95,0.5) 3(-0.95,0) 4(-0.95,-0.5) 5(-0.95,-1) 6(0.95,-1) 7(0.95,-0.5) 8(0.95,0) 9(0.95,0.5) 10(0.95,1)
  rect 0.84x2.4 smd mask+0.07: 11(0,0)
  silkscreen extent -1.6,-1.6 1.1,1.8, body extent -1,-1.5 1,1.5, height 0.8
FID_40X52D [mil]
  round 40 smd paste-40 mask+5.91: 1(0,0)
IHLP_255MILX270MIL [mil]
  rect 72x135 smd: 1(-109,0) 2(109,0)
  silkscreen extent -148,-148 148,148, body extent -135,-130 135,130, height 118
LED_0603 [mm]
  rect 0.8x0.8 smd: 1(-0.8,0) 2(0.8,0)
  silkscreen extent -1.78,-0.76 1.52,0.76, body extent -0.85,-0.4 0.85,0.4, height 0.66
MH_5MMD_2.2MMD [mm]
  round 5 / inner round 3.683 / far side round 5 hole 2.2: 1(0,0)
MLF_3X3_12PINS [mm]
  rect 0.48x0.23 smd mask+0.076: 1(-1.36,1.25) 2(-1.36,0.75) 3(-1.36,0.25) 4(-1.36,-0.25) 5(-1.36,-0.75) 6(-1.36,-1.25) 7(1.36,-1.25) 8(1.36,-0.75) 9(1.36,-0.25) 10(1.36,0.25) 11(1.36,0.75) 12(1.36,1.25)
  rect 1.8x1.125 smd mask+0.025: 13(0,0.699)
  rect 0.4x1.19 smd mask+0.076: 14(-0.77,-0.73)
  rect 0.9x1.19 smd mask+0.025: 15(0.45,-0.73)
  silkscreen extent -2,-1.65 1.52,1.9, body extent -1.52,-1.65 1.52,1.65, height 0.9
